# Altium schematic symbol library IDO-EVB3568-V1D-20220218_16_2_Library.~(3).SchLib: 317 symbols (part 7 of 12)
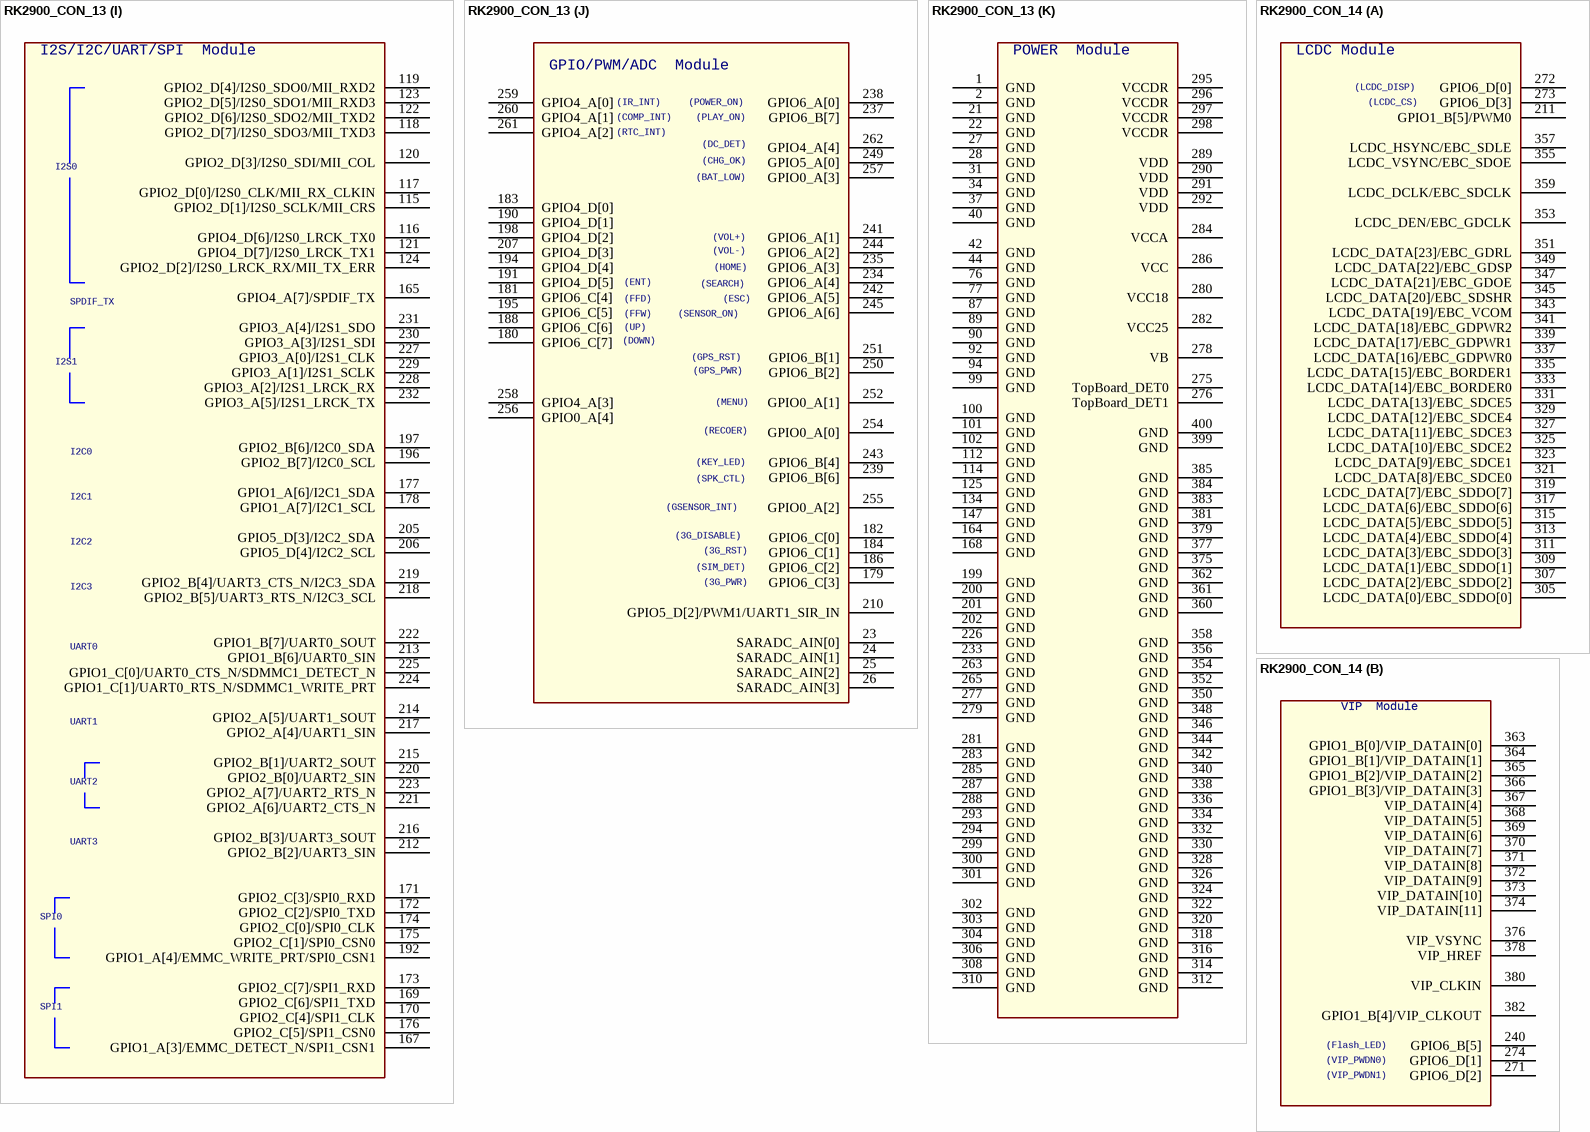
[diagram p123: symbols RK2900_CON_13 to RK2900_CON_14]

## RK2900_CON_13
designator U?
Altium-Right: 240; Altium-Bottom: 690; Altium-Right1: 210; Altium-Bottom1: 440; Altium-Right2: 120; Altium-Bottom2: 650; Altium-Right3: 160; Altium-Bottom3: 390; Altium-Right4: 140; Altium-Bottom4: 270; Altium-Right5: 280; Altium-Bottom5: 520; Altium-Right6: 170; Altium-Right7: 190; Altium-Bottom7: 530; Altium-Right8: 290; Altium-Bottom8: 300; Altium-Right9: 220; Altium-Bottom9: 340; Altium-Right10: 180; Altium-Bottom10: 200
footprint RK2900_TOP
part A pins: 211 GPIO1_B[5]/PWM0, 272 GPIO6_D[0], 273 GPIO6_D[3], 305 LCDC_DATA[0]/EBC_SDDO[0], 307 LCDC_DATA[2]/EBC_SDDO[2], 309 LCDC_DATA[1]/EBC_SDDO[1], 311 LCDC_DATA[3]/EBC_SDDO[3], 313 LCDC_DATA[4]/EBC_SDDO[4], 315 LCDC_DATA[5]/EBC_SDDO[5], 317 LCDC_DATA[6]/EBC_SDDO[6], 319 LCDC_DATA[7]/EBC_SDDO[7], 321 LCDC_DATA[8]/EBC_SDCE0, 323 LCDC_DATA[9]/EBC_SDCE1, 325 LCDC_DATA[10]/EBC_SDCE2, 327 LCDC_DATA[11]/EBC_SDCE3, 329 LCDC_DATA[12]/EBC_SDCE4, 331 LCDC_DATA[13]/EBC_SDCE5, 333 LCDC_DATA[14]/EBC_BORDER0, 335 LCDC_DATA[15]/EBC_BORDER1, 337 LCDC_DATA[16]/EBC_GDPWR0, 339 LCDC_DATA[17]/EBC_GDPWR1, 341 LCDC_DATA[18]/EBC_GDPWR2, 343 LCDC_DATA[19]/EBC_VCOM, 345 LCDC_DATA[20]/EBC_SDSHR, 347 LCDC_DATA[21]/EBC_GDOE, 349 LCDC_DATA[22]/EBC_GDSP, 351 LCDC_DATA[23]/EBC_GDRL, 353 LCDC_DEN/EBC_GDCLK, 355 LCDC_VSYNC/EBC_SDOE, 357 LCDC_HSYNC/EBC_SDLE, 359 LCDC_DCLK/EBC_SDCLK
part B pins: 240 GPIO6_B[5], 271 GPIO6_D[2], 274 GPIO6_D[1], 363 GPIO1_B[0]/VIP_DATAIN[0], 364 GPIO1_B[1]/VIP_DATAIN[1], 365 GPIO1_B[2]/VIP_DATAIN[2], 366 GPIO1_B[3]/VIP_DATAIN[3], 367 VIP_DATAIN[4], 368 VIP_DATAIN[5], 369 VIP_DATAIN[6], 370 VIP_DATAIN[7], 371 VIP_DATAIN[8], 372 VIP_DATAIN[9], 373 VIP_DATAIN[10], 374 VIP_DATAIN[11], 376 VIP_VSYNC, 378 VIP_HREF, 380 VIP_CLKIN, 382 GPIO1_B[4]/VIP_CLKOUT
part C pins: 3 GPIO0_C[6]/EBC_SDCE4/SMC_DATA[14], 4 GPIO0_C[7]/EBC_SDCE5/SMC_DATA[15], 5 GPIO0_C[0]/EBC_GDSP/SMC_DATA[8], 6 GPIO0_C[1]/EBC_GDRL/SMC_DATA[9], 7 GPIO0_B[3]/EBC_BORDER0/SMC_ADDR[3]/HOST_DATA[3], 8 GPIO0_B[4]/EBC_BORDER1/SMC_WEN, 9 GPIO0_D[1]/EBC_GDCLK/SMC_ADDR[4]/HOST_DATA[4], 10 GPIO0_B[2]/EBC_SDCE2/SMC_ADDR[2]/HOST_DATA[2], 11 GPIO0_C[3]/EBC_GDPWR1/SMC_DATA[11], 12 GPIO0_B[7]/EBC_GDOE/SMC_OEN, 13 GPIO0_D[0]/EBC_SDOE/SMC_ADVN, 14 GPIO5_C[6]/EBC_SDDO[6]/SMC_DATA[6], 15 GPIO0_C[5]/EBC_SDCE3/SMC_DATA[13], 16 GPIO0_B[1]/EBC_SDCE1/SMC_ADDR[1]/HOST_DATA[1], 17 GPIO5_C[5]/EBC_SDDO[5]/SMC_DATA[5], 18 GPIO3_D[5]/SMC_ADDR[7]/HOST_DATA[7], 19 GPIO1_A[2]/SMC_CSN1, 20 GPIO0_C[4]/EBC_GDPWR2/SMC_DATA[12], 43 GPIO3_D[6]/SMC_ADDR[8]/HOST_DATA[8], 150 GPIO3_D[4]/HOST_WRN, 151 GPIO3_D[3]/HOST_RDN, 152 GPIO3_D[2]/HOST_CSN, 153 GPIO3_D[7]/SMC_ADDR[9]/HOST_DATA[9], 154 GPIO3_A[6]/SMC_ADDR[14]/HOST_DATA[14], 155 GPIO3_C[7]/SMC_ADDR[17]/HOST_DATA[17], 156 GPIO3_C[3]/SMC_ADDR[10]/HOST_DATA[10], 157 GPIO3_C[4]/SMC_ADDR[11]/HOST_DATA[11], 158 GPIO3_D[1]/SMC_ADDR[19]/HOST_ADDR1, 159 GPIO3_C[5]/SMC_ADDR[12]/HOST_DATA[12], 160 GPIO3_C[2]/SMC_ADDR[13]/HOST_DATA[13], 161 GPIO3_C[6]/SMC_ADDR[16]/HOST_DATA[16], 162 GPIO3_A[7]/SMC_ADDR[15]/HOST_DATA[15], 163 GPIO3_D[0]/SMC_ADDR[18]/HOST_ADDR0, 386 GPIO1_A[1]/SMC_CSN0, 387 GPIO5_C[4]/EBC_SDDO[4]/SMC_DATA[4], 388 GPIO5_D[1]/EBC_SDCLK/SMC_ADDR[6]/HOST_DATA[6], 389 GPIO0_B[5]/EBC_VCOM/SMC_BLSN0, 390 GPIO5_C[0]/EBC_SDDO[0]/SMC_DATA[0], 391 GPIO5_D[0]/EBC_SDLE/SMC_ADDR[5]/HOST_DATA[5], 392 GPIO5_C[1]/EBC_SDDO[1]/SMC_DATA[1], 393 GPIO0_B[6]/EBC_SDSHR/SMC_BLSN1/HOST_INT, 394 GPIO0_C[2]/EBC_GDPWR0/SMC_DATA[10], 395 GPIO5_C[2]/EBC_SDDO[2]/SMC_DATA[2], 396 GPIO5_C[3]/EBC_SDDO[3]/SMC_DATA[3], 397 GPIO5_C[7]/EBC_SDDO[7]/SMC_DATA[7], 398 GPIO0_B[0]/EBC_SDCE0/SMC_ADDR[0]/HOST_DATA[0]
part D pins: 29 OTG_DP, 30 OTG_DM, 32 HOST20_DM, 33 HOST20_DP, 35 HOST11_DM, 36 HOST11_DP, 38 OTG_ID, 39 OTG_VBUS, 41 RTCINT_OUT, 166 GPIO4_A[5]/OTG_DRV_VBUS, 187 GPIO4_A[6]/HOST20_DRV_VBUS, 264 NPOR
part E pins: 45 FLASH_ALE, 46 FLASH_DATA[1], 47 FLASH_RDY, 48 FLASH_RDN, 49 GPIO4_B[4]/FLASH_DATA[12], 50 FLASH_DATA[0], 51 FLASH_DATA[4], 52 GPIO4_B[7]/FLASH_DATA[15], 53 GPIO4_B[5]/FLASH_DATA[13], 54 FLASH_CLE, 55 GPIO4_B[1]/FLASH_DATA[9], 56 FLASH_DATA[5], 57 FLASH_CSN0, 58 FLASH_DATA[6], 59 GPIO4_B[0]/FLASH_DATA[8], 60 FLASH_DATA[7], 61 FLASH_DATA[2], 62 FLASH_DATA[3], 63 GPIO0_D[7]/FLASH_CSN6, 64 FLASH_WP, 65 FLASH_WRN, 66 GPIO4_B[6]/FLASH_DATA[14], 67 GPIO0_D[3]/FLASH_CSN2, 68 GPIO0_D[4]/FLASH_CSN3, 69 GPIO0_D[2]/FLASH_CSN1, 70 GPIO0_D[6]/FLASH_CSN5, 71 GPIO1_A[0]/FLASH_CSN7/MDDR_TQ, 72 GPIO0_A[5]/FLASH_DQS, 73 GPIO0_D[5]/FLASH_CSN4, 74 GPIO4_B[2]/FLASH_DATA[10], 75 GPIO4_B[3]/FLASH_DATA[11], 78 GPIO3_B[3]/EMMC_DATA1, 79 GPIO3_B[1]/EMMC_CMD, 80 GPIO3_B[6]/EMMC_DATA4, 81 GPIO3_C[1]/EMMC_DATA7, 82 GPIO3_B[5]/EMMC_DATA3, 83 GPIO3_B[4]/EMMC_DATA2, 84 GPIO3_B[2]/EMMC_DATA0, 85 GPIO3_C[0]/EMMC_DATA6, 86 GPIO3_B[7]/EMMC_DATA5, 88 GPIO3_B[0]/EMMC_CLKOUT, 203 GPIO1_A[5]/EMMC_PWR_EN/PWM3, 246 GPIO6_A[7]
part F pins: 91 GPIO1_C[2]/SDMMC1_CMD, 93 GPIO1_C[7]/SDMMC1_CLKOUT, 95 GPIO1_C[4]/SDMMC1_DATA1, 96 GPIO1_C[3]/SDMMC1_DATA0, 97 GPIO1_C[6]/SDMMC1_DATA3, 98 GPIO1_C[5]/SDMMC1_DATA2, 103 GPIO1_D[3]/SDMMC0_DATA1, 104 GPIO1_D[1]/SDMMC0_CMD, 105 GPIO1_D[5]/SDMMC0_DATA3, 106 GPIO2_A[1]/SDMMC0_DATA7, 107 GPIO1_D[7]/SDMMC0_DATA5, 108 GPIO1_D[2]/SDMMC0_DATA0, 109 GPIO2_A[0]/SDMMC0_DATA6, 110 GPIO1_D[6]/SDMMC0_DATA4, 111 GPIO1_D[4]/SDMMC0_DATA2, 113 GPIO1_D[0]/SDMMC0_CLKOUT, 185 GPIO5_D[7], 193 GPIO2_A[2]/SDMMC0_DETECT_N, 204 GPIO2_A[3]/SDMMC0_WRITE_PRT/PWM2/UART1_SIR_OUT, 208 GPIO5_D[5]/SDMMC0_PWR_EN, 209 GPIO5_D[6]/SDMMC1_PWR_EN
part G pins: 126 GPIO4_C[7]/RMII_RXD0/MII_RXD0, 127 GPIO4_C[3]/RMII_TXD0/MII_TXD0, 128 GPIO4_C[6]/RMII_RXD1/MII_RXD1, 129 GPIO4_C[1]/RMII_TX_EN/MII_TX_EN, 130 GPIO4_C[0]/RMII_CLKOUT/RMII_CLKIN, 131 GPIO4_C[2]/RMII_TXD1/MII_TXD1, 132 GPIO4_C[5]/RMII_CRS_DVALID/MII_RXD_VALID, 133 GPIO4_C[4]/RMII_RX_ERR/MII_RX_ERR, 148 GPIO5_A[3]/MII_TX_CLKIN, 149 GPIO0_A[6]/MII_MD, 189 GPIO0_A[7]/MII_MDCLK, 236 GPIO5_A[2], 248 GPIO6_B[0], 253 GPIO5_A[1], 266 TRST_N, 267 TCK, 268 TDI, 269 TMS, 270 TDO
part H pins: 135 GPIO5_A[7]/HSADC_DATA2, 136 GPIO5_B[5]/HSADC_DATA8/TS_VALID, 137 GPIO5_A[5]/HSADC_DATA0, 138 GPIO5_B[1]/HSADC_DATA4, 139 GPIO5_B[0]/HSADC_DATA3, 140 GPIO5_A[6]/HSADC_DATA1, 141 GPIO5_B[3]/HSADC_DATA6, 142 GPIO5_B[2]/HSADC_DATA5, 143 GPIO5_B[4]/HSADC_DATA7, 144 GPIO5_A[4]/TS_SYNC, 145 GPIO5_B[6]/HSADC_DATA9/TS_FAIL, 146 GPIO5_B[7]/HSADC_CLKOUT/GPS_CLK, 247 GPIO6_B[3]
part I pins: 115 GPIO2_D[1]/I2S0_SCLK/MII_CRS, 116 GPIO4_D[6]/I2S0_LRCK_TX0, 117 GPIO2_D[0]/I2S0_CLK/MII_RX_CLKIN, 118 GPIO2_D[7]/I2S0_SDO3/MII_TXD3, 119 GPIO2_D[4]/I2S0_SDO0/MII_RXD2, 120 GPIO2_D[3]/I2S0_SDI/MII_COL, 121 GPIO4_D[7]/I2S0_LRCK_TX1, 122 GPIO2_D[6]/I2S0_SDO2/MII_TXD2, 123 GPIO2_D[5]/I2S0_SDO1/MII_RXD3, 124 GPIO2_D[2]/I2S0_LRCK_RX/MII_TX_ERR, 165 GPIO4_A[7]/SPDIF_TX, 167 GPIO1_A[3]/EMMC_DETECT_N/SPI1_CSN1, 169 GPIO2_C[6]/SPI1_TXD, 170 GPIO2_C[4]/SPI1_CLK, 171 GPIO2_C[3]/SPI0_RXD, 172 GPIO2_C[2]/SPI0_TXD, 173 GPIO2_C[7]/SPI1_RXD, 174 GPIO2_C[0]/SPI0_CLK, 175 GPIO2_C[1]/SPI0_CSN0, 176 GPIO2_C[5]/SPI1_CSN0, 177 GPIO1_A[6]/I2C1_SDA, 178 GPIO1_A[7]/I2C1_SCL, 192 GPIO1_A[4]/EMMC_WRITE_PRT/SPI0_CSN1, 196 GPIO2_B[7]/I2C0_SCL, 197 GPIO2_B[6]/I2C0_SDA, 205 GPIO5_D[3]/I2C2_SDA, 206 GPIO5_D[4]/I2C2_SCL, 212 GPIO2_B[2]/UART3_SIN, 213 GPIO1_B[6]/UART0_SIN, 214 GPIO2_A[5]/UART1_SOUT, 215 GPIO2_B[1]/UART2_SOUT, 216 GPIO2_B[3]/UART3_SOUT, 217 GPIO2_A[4]/UART1_SIN, 218 GPIO2_B[5]/UART3_RTS_N/I2C3_SCL, 219 GPIO2_B[4]/UART3_CTS_N/I2C3_SDA, 220 GPIO2_B[0]/UART2_SIN, 221 GPIO2_A[6]/UART2_CTS_N, 222 GPIO1_B[7]/UART0_SOUT, 223 GPIO2_A[7]/UART2_RTS_N, 224 GPIO1_C[1]/UART0_RTS_N/SDMMC1_WRITE_PRT, 225 GPIO1_C[0]/UART0_CTS_N/SDMMC1_DETECT_N, 227 GPIO3_A[0]/I2S1_CLK, 228 GPIO3_A[2]/I2S1_LRCK_RX, 229 GPIO3_A[1]/I2S1_SCLK, 230 GPIO3_A[3]/I2S1_SDI, 231 GPIO3_A[4]/I2S1_SDO, 232 GPIO3_A[5]/I2S1_LRCK_TX
part J pins: 23 SARADC_AIN[0], 24 SARADC_AIN[1], 25 SARADC_AIN[2], 26 SARADC_AIN[3], 179 GPIO6_C[3], 180 GPIO6_C[7], 181 GPIO6_C[4], 182 GPIO6_C[0], 183 GPIO4_D[0], 184 GPIO6_C[1], 186 GPIO6_C[2], 188 GPIO6_C[6], 190 GPIO4_D[1], 191 GPIO4_D[5], 194 GPIO4_D[4], 195 GPIO6_C[5], 198 GPIO4_D[2], 207 GPIO4_D[3], 210 GPIO5_D[2]/PWM1/UART1_SIR_IN, 234 GPIO6_A[4], 235 GPIO6_A[3], 237 GPIO6_B[7], 238 GPIO6_A[0], 239 GPIO6_B[6], 241 GPIO6_A[1], 242 GPIO6_A[5], 243 GPIO6_B[4], 244 GPIO6_A[2], 245 GPIO6_A[6], 249 GPIO5_A[0], 250 GPIO6_B[2], 251 GPIO6_B[1], 252 GPIO0_A[1], 254 GPIO0_A[0], 255 GPIO0_A[2], 256 GPIO0_A[4], 257 GPIO0_A[3], 258 GPIO4_A[3], 259 GPIO4_A[0], 260 GPIO4_A[1], 261 GPIO4_A[2], 262 GPIO4_A[4]
part K pins: 1 GND, 2 GND, 21 GND, 22 GND, 27 GND, 28 GND, 31 GND, 34 GND, 37 GND, 40 GND, 42 GND, 44 GND, 76 GND, 77 GND, 87 GND, 89 GND, 90 GND, 92 GND, 94 GND, 99 GND, 100 GND, 101 GND, 102 GND, 112 GND, 114 GND, 125 GND, 134 GND, 147 GND, 164 GND, 168 GND, 199 GND, 200 GND, 201 GND, 202 GND, 226 GND, 233 GND, 263 GND, 265 GND, 275 TopBoard_DET0, 276 TopBoard_DET1, 277 GND, 278 VB, 279 GND, 280 VCC18, 281 GND, 282 VCC25, 283 GND, 284 VCCA, 285 GND, 286 VCC, 287 GND, 288 GND, 289 VDD, 290 VDD, 291 VDD, 292 VDD, 293 GND, 294 GND, 295 VCCDR, 296 VCCDR, 297 VCCDR, 298 VCCDR, 299 GND, 300 GND, 301 GND, 302 GND, 303 GND, 304 GND, 306 GND, 308 GND, 310 GND, 312 GND, 314 GND, 316 GND, 318 GND, 320 GND, 322 GND, 324 GND, 326 GND, 328 GND, 330 GND, 332 GND, 334 GND, 336 GND, 338 GND, 340 GND, 342 GND, 344 GND, 346 GND, 348 GND, 350 GND, 352 GND, 354 GND, 356 GND, 358 GND, 360 GND, 361 GND, 362 GND, 375 GND, 377 GND, 379 GND, 381 GND, 383 GND, 384 GND, 385 GND, 399 GND, 400 GND

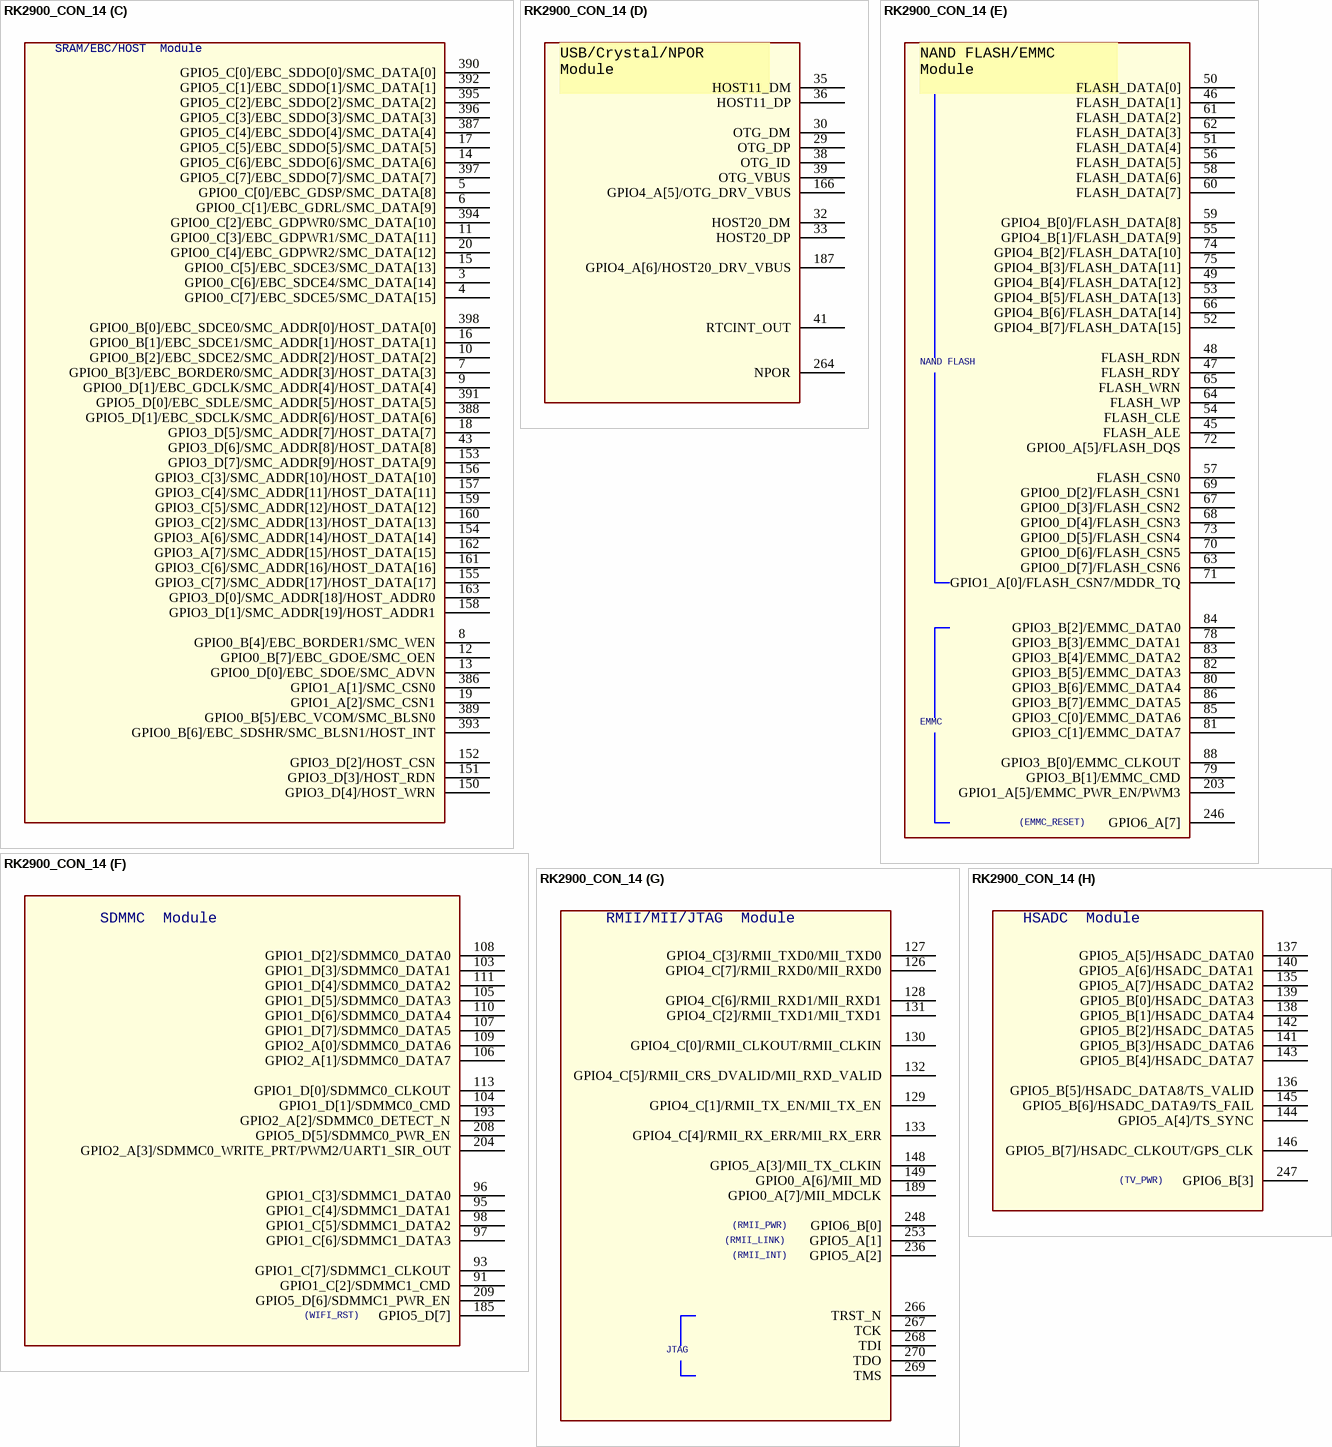
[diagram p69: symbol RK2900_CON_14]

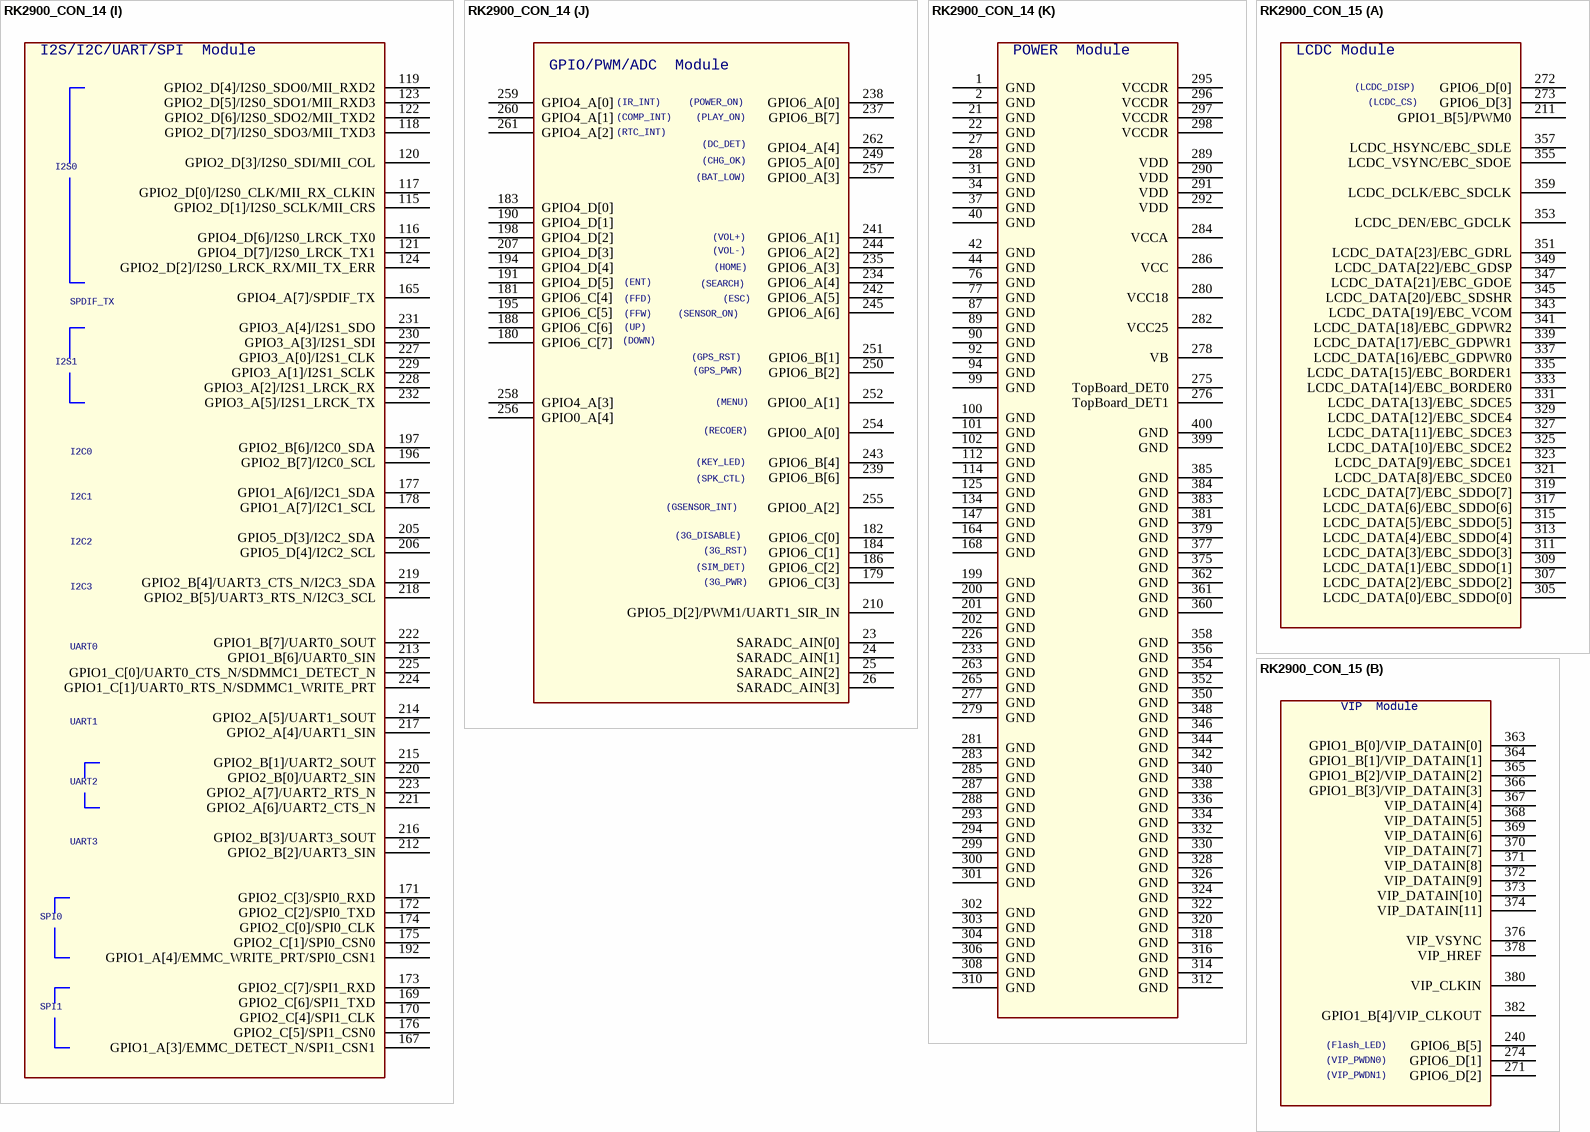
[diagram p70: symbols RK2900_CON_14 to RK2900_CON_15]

## RK2900_CON_14
designator U?
Altium-Right: 210; Altium-Bottom: 440; Altium-Right1: 120; Altium-Bottom1: 650; Altium-Right2: 160; Altium-Bottom2: 390; Altium-Right3: 140; Altium-Bottom3: 270; Altium-Right4: 280; Altium-Bottom4: 520; Altium-Right5: 170; Altium-Bottom5: 240; Altium-Right6: 190; Altium-Bottom6: 530; Altium-Right7: 290; Altium-Bottom7: 300; Altium-Right8: 220; Altium-Bottom8: 340; Altium-Right9: 180; Altium-Bottom9: 200; Altium-Bottom10: 690
footprint RK2900_TOP
part A pins: 211 GPIO1_B[5]/PWM0, 272 GPIO6_D[0], 273 GPIO6_D[3], 305 LCDC_DATA[0]/EBC_SDDO[0], 307 LCDC_DATA[2]/EBC_SDDO[2], 309 LCDC_DATA[1]/EBC_SDDO[1], 311 LCDC_DATA[3]/EBC_SDDO[3], 313 LCDC_DATA[4]/EBC_SDDO[4], 315 LCDC_DATA[5]/EBC_SDDO[5], 317 LCDC_DATA[6]/EBC_SDDO[6], 319 LCDC_DATA[7]/EBC_SDDO[7], 321 LCDC_DATA[8]/EBC_SDCE0, 323 LCDC_DATA[9]/EBC_SDCE1, 325 LCDC_DATA[10]/EBC_SDCE2, 327 LCDC_DATA[11]/EBC_SDCE3, 329 LCDC_DATA[12]/EBC_SDCE4, 331 LCDC_DATA[13]/EBC_SDCE5, 333 LCDC_DATA[14]/EBC_BORDER0, 335 LCDC_DATA[15]/EBC_BORDER1, 337 LCDC_DATA[16]/EBC_GDPWR0, 339 LCDC_DATA[17]/EBC_GDPWR1, 341 LCDC_DATA[18]/EBC_GDPWR2, 343 LCDC_DATA[19]/EBC_VCOM, 345 LCDC_DATA[20]/EBC_SDSHR, 347 LCDC_DATA[21]/EBC_GDOE, 349 LCDC_DATA[22]/EBC_GDSP, 351 LCDC_DATA[23]/EBC_GDRL, 353 LCDC_DEN/EBC_GDCLK, 355 LCDC_VSYNC/EBC_SDOE, 357 LCDC_HSYNC/EBC_SDLE, 359 LCDC_DCLK/EBC_SDCLK
part B pins: 240 GPIO6_B[5], 271 GPIO6_D[2], 274 GPIO6_D[1], 363 GPIO1_B[0]/VIP_DATAIN[0], 364 GPIO1_B[1]/VIP_DATAIN[1], 365 GPIO1_B[2]/VIP_DATAIN[2], 366 GPIO1_B[3]/VIP_DATAIN[3], 367 VIP_DATAIN[4], 368 VIP_DATAIN[5], 369 VIP_DATAIN[6], 370 VIP_DATAIN[7], 371 VIP_DATAIN[8], 372 VIP_DATAIN[9], 373 VIP_DATAIN[10], 374 VIP_DATAIN[11], 376 VIP_VSYNC, 378 VIP_HREF, 380 VIP_CLKIN, 382 GPIO1_B[4]/VIP_CLKOUT
part C pins: 3 GPIO0_C[6]/EBC_SDCE4/SMC_DATA[14], 4 GPIO0_C[7]/EBC_SDCE5/SMC_DATA[15], 5 GPIO0_C[0]/EBC_GDSP/SMC_DATA[8], 6 GPIO0_C[1]/EBC_GDRL/SMC_DATA[9], 7 GPIO0_B[3]/EBC_BORDER0/SMC_ADDR[3]/HOST_DATA[3], 8 GPIO0_B[4]/EBC_BORDER1/SMC_WEN, 9 GPIO0_D[1]/EBC_GDCLK/SMC_ADDR[4]/HOST_DATA[4], 10 GPIO0_B[2]/EBC_SDCE2/SMC_ADDR[2]/HOST_DATA[2], 11 GPIO0_C[3]/EBC_GDPWR1/SMC_DATA[11], 12 GPIO0_B[7]/EBC_GDOE/SMC_OEN, 13 GPIO0_D[0]/EBC_SDOE/SMC_ADVN, 14 GPIO5_C[6]/EBC_SDDO[6]/SMC_DATA[6], 15 GPIO0_C[5]/EBC_SDCE3/SMC_DATA[13], 16 GPIO0_B[1]/EBC_SDCE1/SMC_ADDR[1]/HOST_DATA[1], 17 GPIO5_C[5]/EBC_SDDO[5]/SMC_DATA[5], 18 GPIO3_D[5]/SMC_ADDR[7]/HOST_DATA[7], 19 GPIO1_A[2]/SMC_CSN1, 20 GPIO0_C[4]/EBC_GDPWR2/SMC_DATA[12], 43 GPIO3_D[6]/SMC_ADDR[8]/HOST_DATA[8], 150 GPIO3_D[4]/HOST_WRN, 151 GPIO3_D[3]/HOST_RDN, 152 GPIO3_D[2]/HOST_CSN, 153 GPIO3_D[7]/SMC_ADDR[9]/HOST_DATA[9], 154 GPIO3_A[6]/SMC_ADDR[14]/HOST_DATA[14], 155 GPIO3_C[7]/SMC_ADDR[17]/HOST_DATA[17], 156 GPIO3_C[3]/SMC_ADDR[10]/HOST_DATA[10], 157 GPIO3_C[4]/SMC_ADDR[11]/HOST_DATA[11], 158 GPIO3_D[1]/SMC_ADDR[19]/HOST_ADDR1, 159 GPIO3_C[5]/SMC_ADDR[12]/HOST_DATA[12], 160 GPIO3_C[2]/SMC_ADDR[13]/HOST_DATA[13], 161 GPIO3_C[6]/SMC_ADDR[16]/HOST_DATA[16], 162 GPIO3_A[7]/SMC_ADDR[15]/HOST_DATA[15], 163 GPIO3_D[0]/SMC_ADDR[18]/HOST_ADDR0, 386 GPIO1_A[1]/SMC_CSN0, 387 GPIO5_C[4]/EBC_SDDO[4]/SMC_DATA[4], 388 GPIO5_D[1]/EBC_SDCLK/SMC_ADDR[6]/HOST_DATA[6], 389 GPIO0_B[5]/EBC_VCOM/SMC_BLSN0, 390 GPIO5_C[0]/EBC_SDDO[0]/SMC_DATA[0], 391 GPIO5_D[0]/EBC_SDLE/SMC_ADDR[5]/HOST_DATA[5], 392 GPIO5_C[1]/EBC_SDDO[1]/SMC_DATA[1], 393 GPIO0_B[6]/EBC_SDSHR/SMC_BLSN1/HOST_INT, 394 GPIO0_C[2]/EBC_GDPWR0/SMC_DATA[10], 395 GPIO5_C[2]/EBC_SDDO[2]/SMC_DATA[2], 396 GPIO5_C[3]/EBC_SDDO[3]/SMC_DATA[3], 397 GPIO5_C[7]/EBC_SDDO[7]/SMC_DATA[7], 398 GPIO0_B[0]/EBC_SDCE0/SMC_ADDR[0]/HOST_DATA[0]
part D pins: 29 OTG_DP, 30 OTG_DM, 32 HOST20_DM, 33 HOST20_DP, 35 HOST11_DM, 36 HOST11_DP, 38 OTG_ID, 39 OTG_VBUS, 41 RTCINT_OUT, 166 GPIO4_A[5]/OTG_DRV_VBUS, 187 GPIO4_A[6]/HOST20_DRV_VBUS, 264 NPOR
part E pins: 45 FLASH_ALE, 46 FLASH_DATA[1], 47 FLASH_RDY, 48 FLASH_RDN, 49 GPIO4_B[4]/FLASH_DATA[12], 50 FLASH_DATA[0], 51 FLASH_DATA[4], 52 GPIO4_B[7]/FLASH_DATA[15], 53 GPIO4_B[5]/FLASH_DATA[13], 54 FLASH_CLE, 55 GPIO4_B[1]/FLASH_DATA[9], 56 FLASH_DATA[5], 57 FLASH_CSN0, 58 FLASH_DATA[6], 59 GPIO4_B[0]/FLASH_DATA[8], 60 FLASH_DATA[7], 61 FLASH_DATA[2], 62 FLASH_DATA[3], 63 GPIO0_D[7]/FLASH_CSN6, 64 FLASH_WP, 65 FLASH_WRN, 66 GPIO4_B[6]/FLASH_DATA[14], 67 GPIO0_D[3]/FLASH_CSN2, 68 GPIO0_D[4]/FLASH_CSN3, 69 GPIO0_D[2]/FLASH_CSN1, 70 GPIO0_D[6]/FLASH_CSN5, 71 GPIO1_A[0]/FLASH_CSN7/MDDR_TQ, 72 GPIO0_A[5]/FLASH_DQS, 73 GPIO0_D[5]/FLASH_CSN4, 74 GPIO4_B[2]/FLASH_DATA[10], 75 GPIO4_B[3]/FLASH_DATA[11], 78 GPIO3_B[3]/EMMC_DATA1, 79 GPIO3_B[1]/EMMC_CMD, 80 GPIO3_B[6]/EMMC_DATA4, 81 GPIO3_C[1]/EMMC_DATA7, 82 GPIO3_B[5]/EMMC_DATA3, 83 GPIO3_B[4]/EMMC_DATA2, 84 GPIO3_B[2]/EMMC_DATA0, 85 GPIO3_C[0]/EMMC_DATA6, 86 GPIO3_B[7]/EMMC_DATA5, 88 GPIO3_B[0]/EMMC_CLKOUT, 203 GPIO1_A[5]/EMMC_PWR_EN/PWM3, 246 GPIO6_A[7]
part F pins: 91 GPIO1_C[2]/SDMMC1_CMD, 93 GPIO1_C[7]/SDMMC1_CLKOUT, 95 GPIO1_C[4]/SDMMC1_DATA1, 96 GPIO1_C[3]/SDMMC1_DATA0, 97 GPIO1_C[6]/SDMMC1_DATA3, 98 GPIO1_C[5]/SDMMC1_DATA2, 103 GPIO1_D[3]/SDMMC0_DATA1, 104 GPIO1_D[1]/SDMMC0_CMD, 105 GPIO1_D[5]/SDMMC0_DATA3, 106 GPIO2_A[1]/SDMMC0_DATA7, 107 GPIO1_D[7]/SDMMC0_DATA5, 108 GPIO1_D[2]/SDMMC0_DATA0, 109 GPIO2_A[0]/SDMMC0_DATA6, 110 GPIO1_D[6]/SDMMC0_DATA4, 111 GPIO1_D[4]/SDMMC0_DATA2, 113 GPIO1_D[0]/SDMMC0_CLKOUT, 185 GPIO5_D[7], 193 GPIO2_A[2]/SDMMC0_DETECT_N, 204 GPIO2_A[3]/SDMMC0_WRITE_PRT/PWM2/UART1_SIR_OUT, 208 GPIO5_D[5]/SDMMC0_PWR_EN, 209 GPIO5_D[6]/SDMMC1_PWR_EN
part G pins: 126 GPIO4_C[7]/RMII_RXD0/MII_RXD0, 127 GPIO4_C[3]/RMII_TXD0/MII_TXD0, 128 GPIO4_C[6]/RMII_RXD1/MII_RXD1, 129 GPIO4_C[1]/RMII_TX_EN/MII_TX_EN, 130 GPIO4_C[0]/RMII_CLKOUT/RMII_CLKIN, 131 GPIO4_C[2]/RMII_TXD1/MII_TXD1, 132 GPIO4_C[5]/RMII_CRS_DVALID/MII_RXD_VALID, 133 GPIO4_C[4]/RMII_RX_ERR/MII_RX_ERR, 148 GPIO5_A[3]/MII_TX_CLKIN, 149 GPIO0_A[6]/MII_MD, 189 GPIO0_A[7]/MII_MDCLK, 236 GPIO5_A[2], 248 GPIO6_B[0], 253 GPIO5_A[1], 266 TRST_N, 267 TCK, 268 TDI, 269 TMS, 270 TDO
part H pins: 135 GPIO5_A[7]/HSADC_DATA2, 136 GPIO5_B[5]/HSADC_DATA8/TS_VALID, 137 GPIO5_A[5]/HSADC_DATA0, 138 GPIO5_B[1]/HSADC_DATA4, 139 GPIO5_B[0]/HSADC_DATA3, 140 GPIO5_A[6]/HSADC_DATA1, 141 GPIO5_B[3]/HSADC_DATA6, 142 GPIO5_B[2]/HSADC_DATA5, 143 GPIO5_B[4]/HSADC_DATA7, 144 GPIO5_A[4]/TS_SYNC, 145 GPIO5_B[6]/HSADC_DATA9/TS_FAIL, 146 GPIO5_B[7]/HSADC_CLKOUT/GPS_CLK, 247 GPIO6_B[3]
part I pins: 115 GPIO2_D[1]/I2S0_SCLK/MII_CRS, 116 GPIO4_D[6]/I2S0_LRCK_TX0, 117 GPIO2_D[0]/I2S0_CLK/MII_RX_CLKIN, 118 GPIO2_D[7]/I2S0_SDO3/MII_TXD3, 119 GPIO2_D[4]/I2S0_SDO0/MII_RXD2, 120 GPIO2_D[3]/I2S0_SDI/MII_COL, 121 GPIO4_D[7]/I2S0_LRCK_TX1, 122 GPIO2_D[6]/I2S0_SDO2/MII_TXD2, 123 GPIO2_D[5]/I2S0_SDO1/MII_RXD3, 124 GPIO2_D[2]/I2S0_LRCK_RX/MII_TX_ERR, 165 GPIO4_A[7]/SPDIF_TX, 167 GPIO1_A[3]/EMMC_DETECT_N/SPI1_CSN1, 169 GPIO2_C[6]/SPI1_TXD, 170 GPIO2_C[4]/SPI1_CLK, 171 GPIO2_C[3]/SPI0_RXD, 172 GPIO2_C[2]/SPI0_TXD, 173 GPIO2_C[7]/SPI1_RXD, 174 GPIO2_C[0]/SPI0_CLK, 175 GPIO2_C[1]/SPI0_CSN0, 176 GPIO2_C[5]/SPI1_CSN0, 177 GPIO1_A[6]/I2C1_SDA, 178 GPIO1_A[7]/I2C1_SCL, 192 GPIO1_A[4]/EMMC_WRITE_PRT/SPI0_CSN1, 196 GPIO2_B[7]/I2C0_SCL, 197 GPIO2_B[6]/I2C0_SDA, 205 GPIO5_D[3]/I2C2_SDA, 206 GPIO5_D[4]/I2C2_SCL, 212 GPIO2_B[2]/UART3_SIN, 213 GPIO1_B[6]/UART0_SIN, 214 GPIO2_A[5]/UART1_SOUT, 215 GPIO2_B[1]/UART2_SOUT, 216 GPIO2_B[3]/UART3_SOUT, 217 GPIO2_A[4]/UART1_SIN, 218 GPIO2_B[5]/UART3_RTS_N/I2C3_SCL, 219 GPIO2_B[4]/UART3_CTS_N/I2C3_SDA, 220 GPIO2_B[0]/UART2_SIN, 221 GPIO2_A[6]/UART2_CTS_N, 222 GPIO1_B[7]/UART0_SOUT, 223 GPIO2_A[7]/UART2_RTS_N, 224 GPIO1_C[1]/UART0_RTS_N/SDMMC1_WRITE_PRT, 225 GPIO1_C[0]/UART0_CTS_N/SDMMC1_DETECT_N, 227 GPIO3_A[0]/I2S1_CLK, 228 GPIO3_A[2]/I2S1_LRCK_RX, 229 GPIO3_A[1]/I2S1_SCLK, 230 GPIO3_A[3]/I2S1_SDI, 231 GPIO3_A[4]/I2S1_SDO, 232 GPIO3_A[5]/I2S1_LRCK_TX
part J pins: 23 SARADC_AIN[0], 24 SARADC_AIN[1], 25 SARADC_AIN[2], 26 SARADC_AIN[3], 179 GPIO6_C[3], 180 GPIO6_C[7], 181 GPIO6_C[4], 182 GPIO6_C[0], 183 GPIO4_D[0], 184 GPIO6_C[1], 186 GPIO6_C[2], 188 GPIO6_C[6], 190 GPIO4_D[1], 191 GPIO4_D[5], 194 GPIO4_D[4], 195 GPIO6_C[5], 198 GPIO4_D[2], 207 GPIO4_D[3], 210 GPIO5_D[2]/PWM1/UART1_SIR_IN, 234 GPIO6_A[4], 235 GPIO6_A[3], 237 GPIO6_B[7], 238 GPIO6_A[0], 239 GPIO6_B[6], 241 GPIO6_A[1], 242 GPIO6_A[5], 243 GPIO6_B[4], 244 GPIO6_A[2], 245 GPIO6_A[6], 249 GPIO5_A[0], 250 GPIO6_B[2], 251 GPIO6_B[1], 252 GPIO0_A[1], 254 GPIO0_A[0], 255 GPIO0_A[2], 256 GPIO0_A[4], 257 GPIO0_A[3], 258 GPIO4_A[3], 259 GPIO4_A[0], 260 GPIO4_A[1], 261 GPIO4_A[2], 262 GPIO4_A[4]
part K pins: 1 GND, 2 GND, 21 GND, 22 GND, 27 GND, 28 GND, 31 GND, 34 GND, 37 GND, 40 GND, 42 GND, 44 GND, 76 GND, 77 GND, 87 GND, 89 GND, 90 GND, 92 GND, 94 GND, 99 GND, 100 GND, 101 GND, 102 GND, 112 GND, 114 GND, 125 GND, 134 GND, 147 GND, 164 GND, 168 GND, 199 GND, 200 GND, 201 GND, 202 GND, 226 GND, 233 GND, 263 GND, 265 GND, 275 TopBoard_DET0, 276 TopBoard_DET1, 277 GND, 278 VB, 279 GND, 280 VCC18, 281 GND, 282 VCC25, 283 GND, 284 VCCA, 285 GND, 286 VCC, 287 GND, 288 GND, 289 VDD, 290 VDD, 291 VDD, 292 VDD, 293 GND, 294 GND, 295 VCCDR, 296 VCCDR, 297 VCCDR, 298 VCCDR, 299 GND, 300 GND, 301 GND, 302 GND, 303 GND, 304 GND, 306 GND, 308 GND, 310 GND, 312 GND, 314 GND, 316 GND, 318 GND, 320 GND, 322 GND, 324 GND, 326 GND, 328 GND, 330 GND, 332 GND, 334 GND, 336 GND, 338 GND, 340 GND, 342 GND, 344 GND, 346 GND, 348 GND, 350 GND, 352 GND, 354 GND, 356 GND, 358 GND, 360 GND, 361 GND, 362 GND, 375 GND, 377 GND, 379 GND, 381 GND, 383 GND, 384 GND, 385 GND, 399 GND, 400 GND

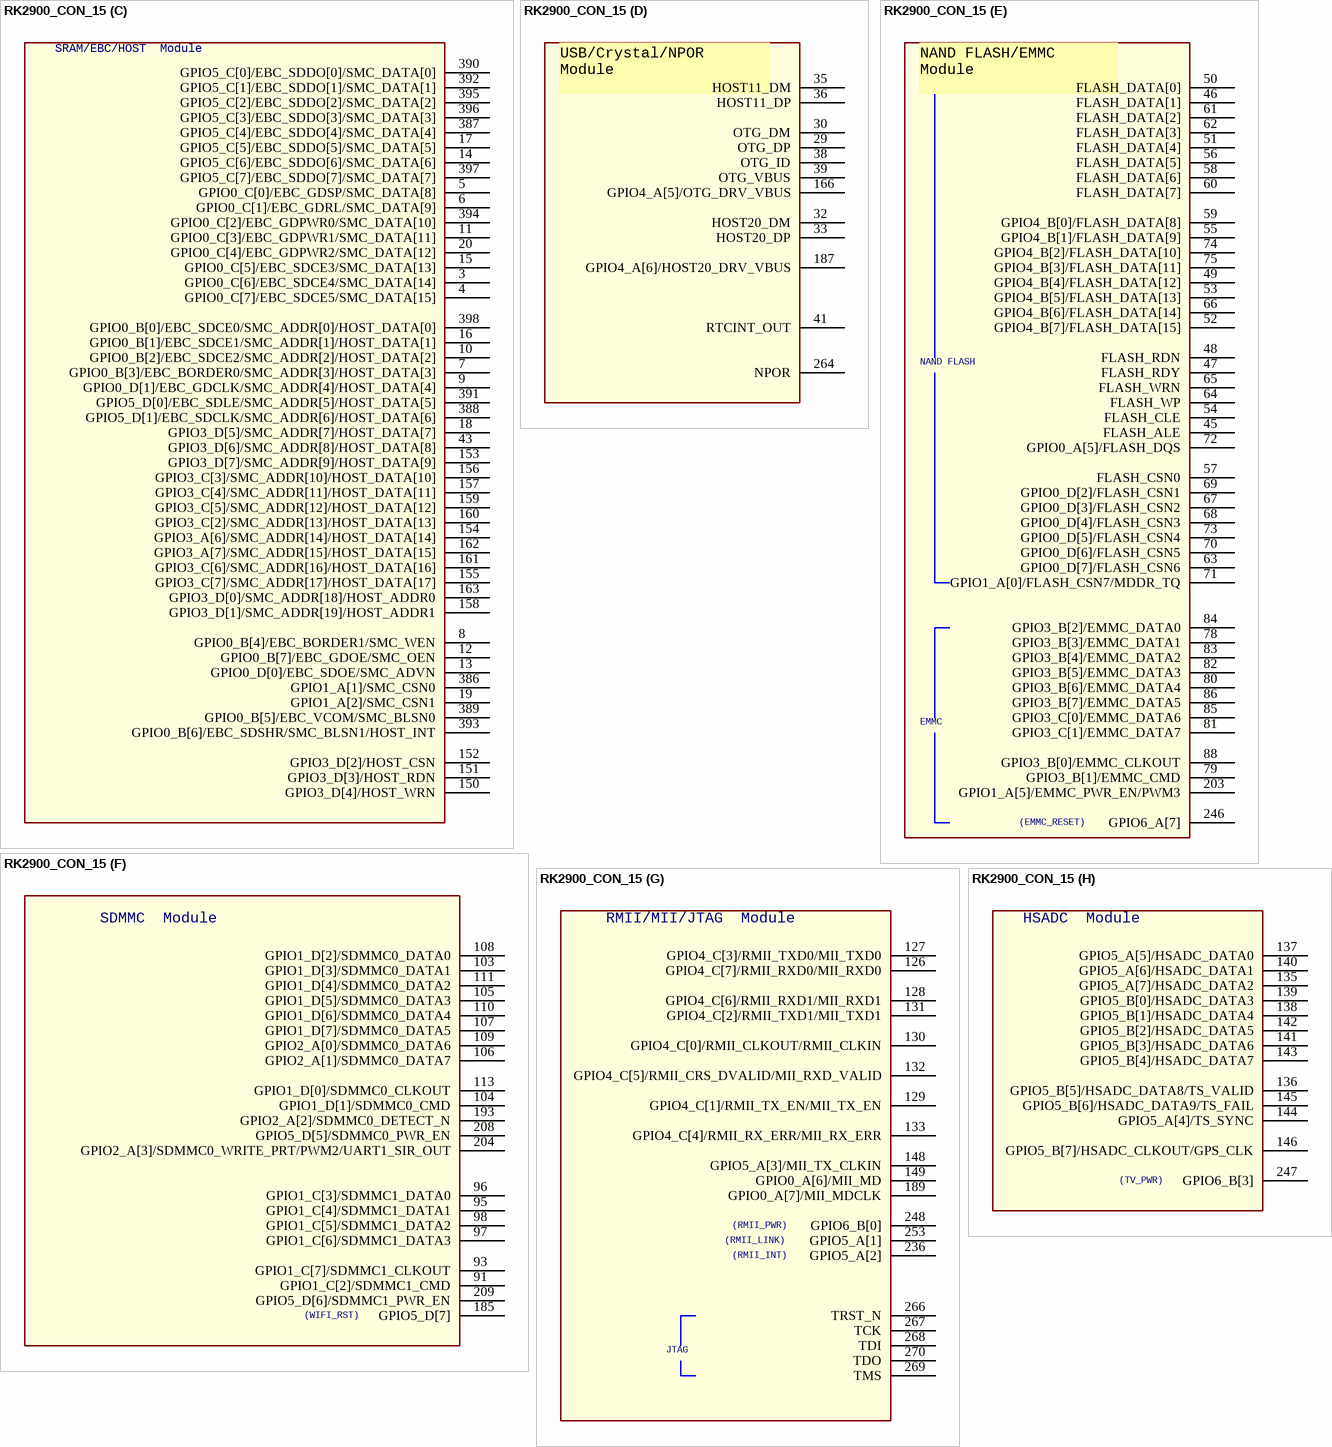
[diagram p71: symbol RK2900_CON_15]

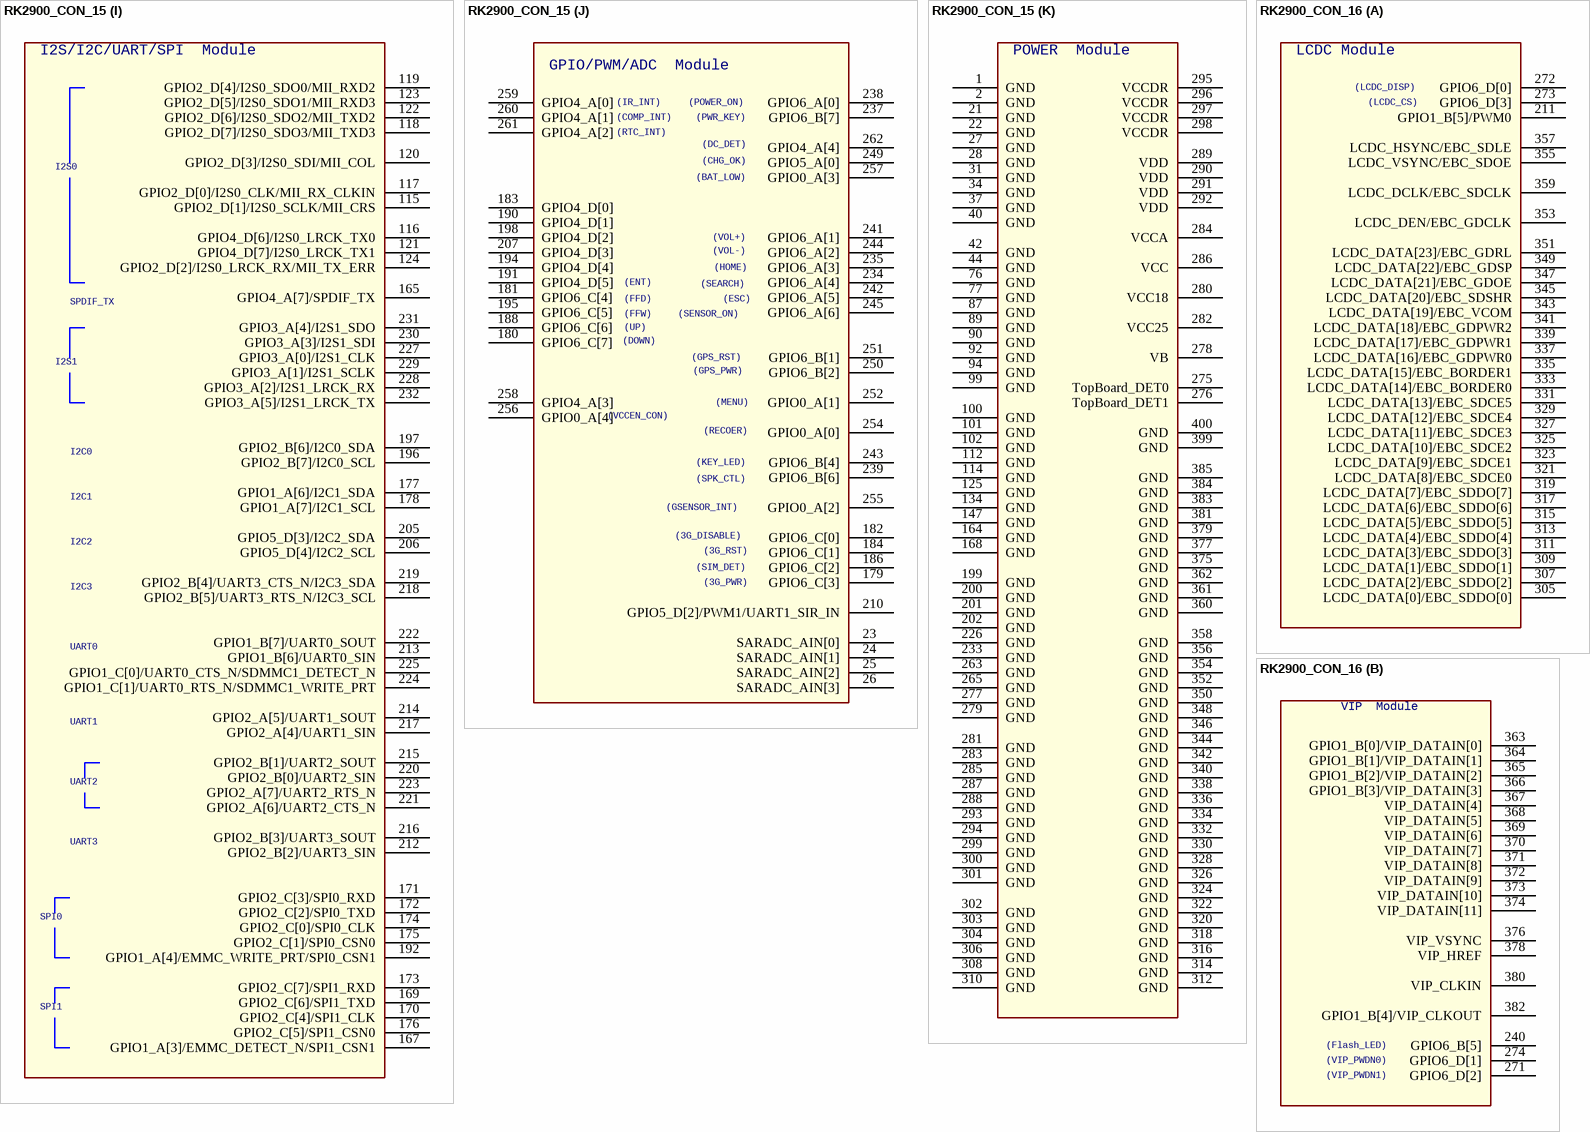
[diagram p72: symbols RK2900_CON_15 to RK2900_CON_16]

## RK2900_CON_15
designator U?
Altium-Right: 120; Altium-Bottom: 650; Altium-Right1: 160; Altium-Bottom1: 390; Altium-Right2: 140; Altium-Bottom2: 270; Altium-Right3: 280; Altium-Bottom3: 520; Altium-Right4: 170; Altium-Bottom4: 240; Altium-Right5: 190; Altium-Bottom5: 530; Altium-Right6: 290; Altium-Bottom6: 300; Altium-Right7: 220; Altium-Bottom7: 340; Altium-Right8: 180; Altium-Bottom8: 200; Altium-Bottom9: 690; Altium-Right10: 210; Altium-Bottom10: 440
footprint RK2900_TOP
part A pins: 211 GPIO1_B[5]/PWM0, 272 GPIO6_D[0], 273 GPIO6_D[3], 305 LCDC_DATA[0]/EBC_SDDO[0], 307 LCDC_DATA[2]/EBC_SDDO[2], 309 LCDC_DATA[1]/EBC_SDDO[1], 311 LCDC_DATA[3]/EBC_SDDO[3], 313 LCDC_DATA[4]/EBC_SDDO[4], 315 LCDC_DATA[5]/EBC_SDDO[5], 317 LCDC_DATA[6]/EBC_SDDO[6], 319 LCDC_DATA[7]/EBC_SDDO[7], 321 LCDC_DATA[8]/EBC_SDCE0, 323 LCDC_DATA[9]/EBC_SDCE1, 325 LCDC_DATA[10]/EBC_SDCE2, 327 LCDC_DATA[11]/EBC_SDCE3, 329 LCDC_DATA[12]/EBC_SDCE4, 331 LCDC_DATA[13]/EBC_SDCE5, 333 LCDC_DATA[14]/EBC_BORDER0, 335 LCDC_DATA[15]/EBC_BORDER1, 337 LCDC_DATA[16]/EBC_GDPWR0, 339 LCDC_DATA[17]/EBC_GDPWR1, 341 LCDC_DATA[18]/EBC_GDPWR2, 343 LCDC_DATA[19]/EBC_VCOM, 345 LCDC_DATA[20]/EBC_SDSHR, 347 LCDC_DATA[21]/EBC_GDOE, 349 LCDC_DATA[22]/EBC_GDSP, 351 LCDC_DATA[23]/EBC_GDRL, 353 LCDC_DEN/EBC_GDCLK, 355 LCDC_VSYNC/EBC_SDOE, 357 LCDC_HSYNC/EBC_SDLE, 359 LCDC_DCLK/EBC_SDCLK
part B pins: 240 GPIO6_B[5], 271 GPIO6_D[2], 274 GPIO6_D[1], 363 GPIO1_B[0]/VIP_DATAIN[0], 364 GPIO1_B[1]/VIP_DATAIN[1], 365 GPIO1_B[2]/VIP_DATAIN[2], 366 GPIO1_B[3]/VIP_DATAIN[3], 367 VIP_DATAIN[4], 368 VIP_DATAIN[5], 369 VIP_DATAIN[6], 370 VIP_DATAIN[7], 371 VIP_DATAIN[8], 372 VIP_DATAIN[9], 373 VIP_DATAIN[10], 374 VIP_DATAIN[11], 376 VIP_VSYNC, 378 VIP_HREF, 380 VIP_CLKIN, 382 GPIO1_B[4]/VIP_CLKOUT
part C pins: 3 GPIO0_C[6]/EBC_SDCE4/SMC_DATA[14], 4 GPIO0_C[7]/EBC_SDCE5/SMC_DATA[15], 5 GPIO0_C[0]/EBC_GDSP/SMC_DATA[8], 6 GPIO0_C[1]/EBC_GDRL/SMC_DATA[9], 7 GPIO0_B[3]/EBC_BORDER0/SMC_ADDR[3]/HOST_DATA[3], 8 GPIO0_B[4]/EBC_BORDER1/SMC_WEN, 9 GPIO0_D[1]/EBC_GDCLK/SMC_ADDR[4]/HOST_DATA[4], 10 GPIO0_B[2]/EBC_SDCE2/SMC_ADDR[2]/HOST_DATA[2], 11 GPIO0_C[3]/EBC_GDPWR1/SMC_DATA[11], 12 GPIO0_B[7]/EBC_GDOE/SMC_OEN, 13 GPIO0_D[0]/EBC_SDOE/SMC_ADVN, 14 GPIO5_C[6]/EBC_SDDO[6]/SMC_DATA[6], 15 GPIO0_C[5]/EBC_SDCE3/SMC_DATA[13], 16 GPIO0_B[1]/EBC_SDCE1/SMC_ADDR[1]/HOST_DATA[1], 17 GPIO5_C[5]/EBC_SDDO[5]/SMC_DATA[5], 18 GPIO3_D[5]/SMC_ADDR[7]/HOST_DATA[7], 19 GPIO1_A[2]/SMC_CSN1, 20 GPIO0_C[4]/EBC_GDPWR2/SMC_DATA[12], 43 GPIO3_D[6]/SMC_ADDR[8]/HOST_DATA[8], 150 GPIO3_D[4]/HOST_WRN, 151 GPIO3_D[3]/HOST_RDN, 152 GPIO3_D[2]/HOST_CSN, 153 GPIO3_D[7]/SMC_ADDR[9]/HOST_DATA[9], 154 GPIO3_A[6]/SMC_ADDR[14]/HOST_DATA[14], 155 GPIO3_C[7]/SMC_ADDR[17]/HOST_DATA[17], 156 GPIO3_C[3]/SMC_ADDR[10]/HOST_DATA[10], 157 GPIO3_C[4]/SMC_ADDR[11]/HOST_DATA[11], 158 GPIO3_D[1]/SMC_ADDR[19]/HOST_ADDR1, 159 GPIO3_C[5]/SMC_ADDR[12]/HOST_DATA[12], 160 GPIO3_C[2]/SMC_ADDR[13]/HOST_DATA[13], 161 GPIO3_C[6]/SMC_ADDR[16]/HOST_DATA[16], 162 GPIO3_A[7]/SMC_ADDR[15]/HOST_DATA[15], 163 GPIO3_D[0]/SMC_ADDR[18]/HOST_ADDR0, 386 GPIO1_A[1]/SMC_CSN0, 387 GPIO5_C[4]/EBC_SDDO[4]/SMC_DATA[4], 388 GPIO5_D[1]/EBC_SDCLK/SMC_ADDR[6]/HOST_DATA[6], 389 GPIO0_B[5]/EBC_VCOM/SMC_BLSN0, 390 GPIO5_C[0]/EBC_SDDO[0]/SMC_DATA[0], 391 GPIO5_D[0]/EBC_SDLE/SMC_ADDR[5]/HOST_DATA[5], 392 GPIO5_C[1]/EBC_SDDO[1]/SMC_DATA[1], 393 GPIO0_B[6]/EBC_SDSHR/SMC_BLSN1/HOST_INT, 394 GPIO0_C[2]/EBC_GDPWR0/SMC_DATA[10], 395 GPIO5_C[2]/EBC_SDDO[2]/SMC_DATA[2], 396 GPIO5_C[3]/EBC_SDDO[3]/SMC_DATA[3], 397 GPIO5_C[7]/EBC_SDDO[7]/SMC_DATA[7], 398 GPIO0_B[0]/EBC_SDCE0/SMC_ADDR[0]/HOST_DATA[0]
part D pins: 29 OTG_DP, 30 OTG_DM, 32 HOST20_DM, 33 HOST20_DP, 35 HOST11_DM, 36 HOST11_DP, 38 OTG_ID, 39 OTG_VBUS, 41 RTCINT_OUT, 166 GPIO4_A[5]/OTG_DRV_VBUS, 187 GPIO4_A[6]/HOST20_DRV_VBUS, 264 NPOR
part E pins: 45 FLASH_ALE, 46 FLASH_DATA[1], 47 FLASH_RDY, 48 FLASH_RDN, 49 GPIO4_B[4]/FLASH_DATA[12], 50 FLASH_DATA[0], 51 FLASH_DATA[4], 52 GPIO4_B[7]/FLASH_DATA[15], 53 GPIO4_B[5]/FLASH_DATA[13], 54 FLASH_CLE, 55 GPIO4_B[1]/FLASH_DATA[9], 56 FLASH_DATA[5], 57 FLASH_CSN0, 58 FLASH_DATA[6], 59 GPIO4_B[0]/FLASH_DATA[8], 60 FLASH_DATA[7], 61 FLASH_DATA[2], 62 FLASH_DATA[3], 63 GPIO0_D[7]/FLASH_CSN6, 64 FLASH_WP, 65 FLASH_WRN, 66 GPIO4_B[6]/FLASH_DATA[14], 67 GPIO0_D[3]/FLASH_CSN2, 68 GPIO0_D[4]/FLASH_CSN3, 69 GPIO0_D[2]/FLASH_CSN1, 70 GPIO0_D[6]/FLASH_CSN5, 71 GPIO1_A[0]/FLASH_CSN7/MDDR_TQ, 72 GPIO0_A[5]/FLASH_DQS, 73 GPIO0_D[5]/FLASH_CSN4, 74 GPIO4_B[2]/FLASH_DATA[10], 75 GPIO4_B[3]/FLASH_DATA[11], 78 GPIO3_B[3]/EMMC_DATA1, 79 GPIO3_B[1]/EMMC_CMD, 80 GPIO3_B[6]/EMMC_DATA4, 81 GPIO3_C[1]/EMMC_DATA7, 82 GPIO3_B[5]/EMMC_DATA3, 83 GPIO3_B[4]/EMMC_DATA2, 84 GPIO3_B[2]/EMMC_DATA0, 85 GPIO3_C[0]/EMMC_DATA6, 86 GPIO3_B[7]/EMMC_DATA5, 88 GPIO3_B[0]/EMMC_CLKOUT, 203 GPIO1_A[5]/EMMC_PWR_EN/PWM3, 246 GPIO6_A[7]
part F pins: 91 GPIO1_C[2]/SDMMC1_CMD, 93 GPIO1_C[7]/SDMMC1_CLKOUT, 95 GPIO1_C[4]/SDMMC1_DATA1, 96 GPIO1_C[3]/SDMMC1_DATA0, 97 GPIO1_C[6]/SDMMC1_DATA3, 98 GPIO1_C[5]/SDMMC1_DATA2, 103 GPIO1_D[3]/SDMMC0_DATA1, 104 GPIO1_D[1]/SDMMC0_CMD, 105 GPIO1_D[5]/SDMMC0_DATA3, 106 GPIO2_A[1]/SDMMC0_DATA7, 107 GPIO1_D[7]/SDMMC0_DATA5, 108 GPIO1_D[2]/SDMMC0_DATA0, 109 GPIO2_A[0]/SDMMC0_DATA6, 110 GPIO1_D[6]/SDMMC0_DATA4, 111 GPIO1_D[4]/SDMMC0_DATA2, 113 GPIO1_D[0]/SDMMC0_CLKOUT, 185 GPIO5_D[7], 193 GPIO2_A[2]/SDMMC0_DETECT_N, 204 GPIO2_A[3]/SDMMC0_WRITE_PRT/PWM2/UART1_SIR_OUT, 208 GPIO5_D[5]/SDMMC0_PWR_EN, 209 GPIO5_D[6]/SDMMC1_PWR_EN
part G pins: 126 GPIO4_C[7]/RMII_RXD0/MII_RXD0, 127 GPIO4_C[3]/RMII_TXD0/MII_TXD0, 128 GPIO4_C[6]/RMII_RXD1/MII_RXD1, 129 GPIO4_C[1]/RMII_TX_EN/MII_TX_EN, 130 GPIO4_C[0]/RMII_CLKOUT/RMII_CLKIN, 131 GPIO4_C[2]/RMII_TXD1/MII_TXD1, 132 GPIO4_C[5]/RMII_CRS_DVALID/MII_RXD_VALID, 133 GPIO4_C[4]/RMII_RX_ERR/MII_RX_ERR, 148 GPIO5_A[3]/MII_TX_CLKIN, 149 GPIO0_A[6]/MII_MD, 189 GPIO0_A[7]/MII_MDCLK, 236 GPIO5_A[2], 248 GPIO6_B[0], 253 GPIO5_A[1], 266 TRST_N, 267 TCK, 268 TDI, 269 TMS, 270 TDO
part H pins: 135 GPIO5_A[7]/HSADC_DATA2, 136 GPIO5_B[5]/HSADC_DATA8/TS_VALID, 137 GPIO5_A[5]/HSADC_DATA0, 138 GPIO5_B[1]/HSADC_DATA4, 139 GPIO5_B[0]/HSADC_DATA3, 140 GPIO5_A[6]/HSADC_DATA1, 141 GPIO5_B[3]/HSADC_DATA6, 142 GPIO5_B[2]/HSADC_DATA5, 143 GPIO5_B[4]/HSADC_DATA7, 144 GPIO5_A[4]/TS_SYNC, 145 GPIO5_B[6]/HSADC_DATA9/TS_FAIL, 146 GPIO5_B[7]/HSADC_CLKOUT/GPS_CLK, 247 GPIO6_B[3]
part I pins: 115 GPIO2_D[1]/I2S0_SCLK/MII_CRS, 116 GPIO4_D[6]/I2S0_LRCK_TX0, 117 GPIO2_D[0]/I2S0_CLK/MII_RX_CLKIN, 118 GPIO2_D[7]/I2S0_SDO3/MII_TXD3, 119 GPIO2_D[4]/I2S0_SDO0/MII_RXD2, 120 GPIO2_D[3]/I2S0_SDI/MII_COL, 121 GPIO4_D[7]/I2S0_LRCK_TX1, 122 GPIO2_D[6]/I2S0_SDO2/MII_TXD2, 123 GPIO2_D[5]/I2S0_SDO1/MII_RXD3, 124 GPIO2_D[2]/I2S0_LRCK_RX/MII_TX_ERR, 165 GPIO4_A[7]/SPDIF_TX, 167 GPIO1_A[3]/EMMC_DETECT_N/SPI1_CSN1, 169 GPIO2_C[6]/SPI1_TXD, 170 GPIO2_C[4]/SPI1_CLK, 171 GPIO2_C[3]/SPI0_RXD, 172 GPIO2_C[2]/SPI0_TXD, 173 GPIO2_C[7]/SPI1_RXD, 174 GPIO2_C[0]/SPI0_CLK, 175 GPIO2_C[1]/SPI0_CSN0, 176 GPIO2_C[5]/SPI1_CSN0, 177 GPIO1_A[6]/I2C1_SDA, 178 GPIO1_A[7]/I2C1_SCL, 192 GPIO1_A[4]/EMMC_WRITE_PRT/SPI0_CSN1, 196 GPIO2_B[7]/I2C0_SCL, 197 GPIO2_B[6]/I2C0_SDA, 205 GPIO5_D[3]/I2C2_SDA, 206 GPIO5_D[4]/I2C2_SCL, 212 GPIO2_B[2]/UART3_SIN, 213 GPIO1_B[6]/UART0_SIN, 214 GPIO2_A[5]/UART1_SOUT, 215 GPIO2_B[1]/UART2_SOUT, 216 GPIO2_B[3]/UART3_SOUT, 217 GPIO2_A[4]/UART1_SIN, 218 GPIO2_B[5]/UART3_RTS_N/I2C3_SCL, 219 GPIO2_B[4]/UART3_CTS_N/I2C3_SDA, 220 GPIO2_B[0]/UART2_SIN, 221 GPIO2_A[6]/UART2_CTS_N, 222 GPIO1_B[7]/UART0_SOUT, 223 GPIO2_A[7]/UART2_RTS_N, 224 GPIO1_C[1]/UART0_RTS_N/SDMMC1_WRITE_PRT, 225 GPIO1_C[0]/UART0_CTS_N/SDMMC1_DETECT_N, 227 GPIO3_A[0]/I2S1_CLK, 228 GPIO3_A[2]/I2S1_LRCK_RX, 229 GPIO3_A[1]/I2S1_SCLK, 230 GPIO3_A[3]/I2S1_SDI, 231 GPIO3_A[4]/I2S1_SDO, 232 GPIO3_A[5]/I2S1_LRCK_TX
part J pins: 23 SARADC_AIN[0], 24 SARADC_AIN[1], 25 SARADC_AIN[2], 26 SARADC_AIN[3], 179 GPIO6_C[3], 180 GPIO6_C[7], 181 GPIO6_C[4], 182 GPIO6_C[0], 183 GPIO4_D[0], 184 GPIO6_C[1], 186 GPIO6_C[2], 188 GPIO6_C[6], 190 GPIO4_D[1], 191 GPIO4_D[5], 194 GPIO4_D[4], 195 GPIO6_C[5], 198 GPIO4_D[2], 207 GPIO4_D[3], 210 GPIO5_D[2]/PWM1/UART1_SIR_IN, 234 GPIO6_A[4], 235 GPIO6_A[3], 237 GPIO6_B[7], 238 GPIO6_A[0], 239 GPIO6_B[6], 241 GPIO6_A[1], 242 GPIO6_A[5], 243 GPIO6_B[4], 244 GPIO6_A[2], 245 GPIO6_A[6], 249 GPIO5_A[0], 250 GPIO6_B[2], 251 GPIO6_B[1], 252 GPIO0_A[1], 254 GPIO0_A[0], 255 GPIO0_A[2], 256 GPIO0_A[4], 257 GPIO0_A[3], 258 GPIO4_A[3], 259 GPIO4_A[0], 260 GPIO4_A[1], 261 GPIO4_A[2], 262 GPIO4_A[4]
part K pins: 1 GND, 2 GND, 21 GND, 22 GND, 27 GND, 28 GND, 31 GND, 34 GND, 37 GND, 40 GND, 42 GND, 44 GND, 76 GND, 77 GND, 87 GND, 89 GND, 90 GND, 92 GND, 94 GND, 99 GND, 100 GND, 101 GND, 102 GND, 112 GND, 114 GND, 125 GND, 134 GND, 147 GND, 164 GND, 168 GND, 199 GND, 200 GND, 201 GND, 202 GND, 226 GND, 233 GND, 263 GND, 265 GND, 275 TopBoard_DET0, 276 TopBoard_DET1, 277 GND, 278 VB, 279 GND, 280 VCC18, 281 GND, 282 VCC25, 283 GND, 284 VCCA, 285 GND, 286 VCC, 287 GND, 288 GND, 289 VDD, 290 VDD, 291 VDD, 292 VDD, 293 GND, 294 GND, 295 VCCDR, 296 VCCDR, 297 VCCDR, 298 VCCDR, 299 GND, 300 GND, 301 GND, 302 GND, 303 GND, 304 GND, 306 GND, 308 GND, 310 GND, 312 GND, 314 GND, 316 GND, 318 GND, 320 GND, 322 GND, 324 GND, 326 GND, 328 GND, 330 GND, 332 GND, 334 GND, 336 GND, 338 GND, 340 GND, 342 GND, 344 GND, 346 GND, 348 GND, 350 GND, 352 GND, 354 GND, 356 GND, 358 GND, 360 GND, 361 GND, 362 GND, 375 GND, 377 GND, 379 GND, 381 GND, 383 GND, 384 GND, 385 GND, 399 GND, 400 GND

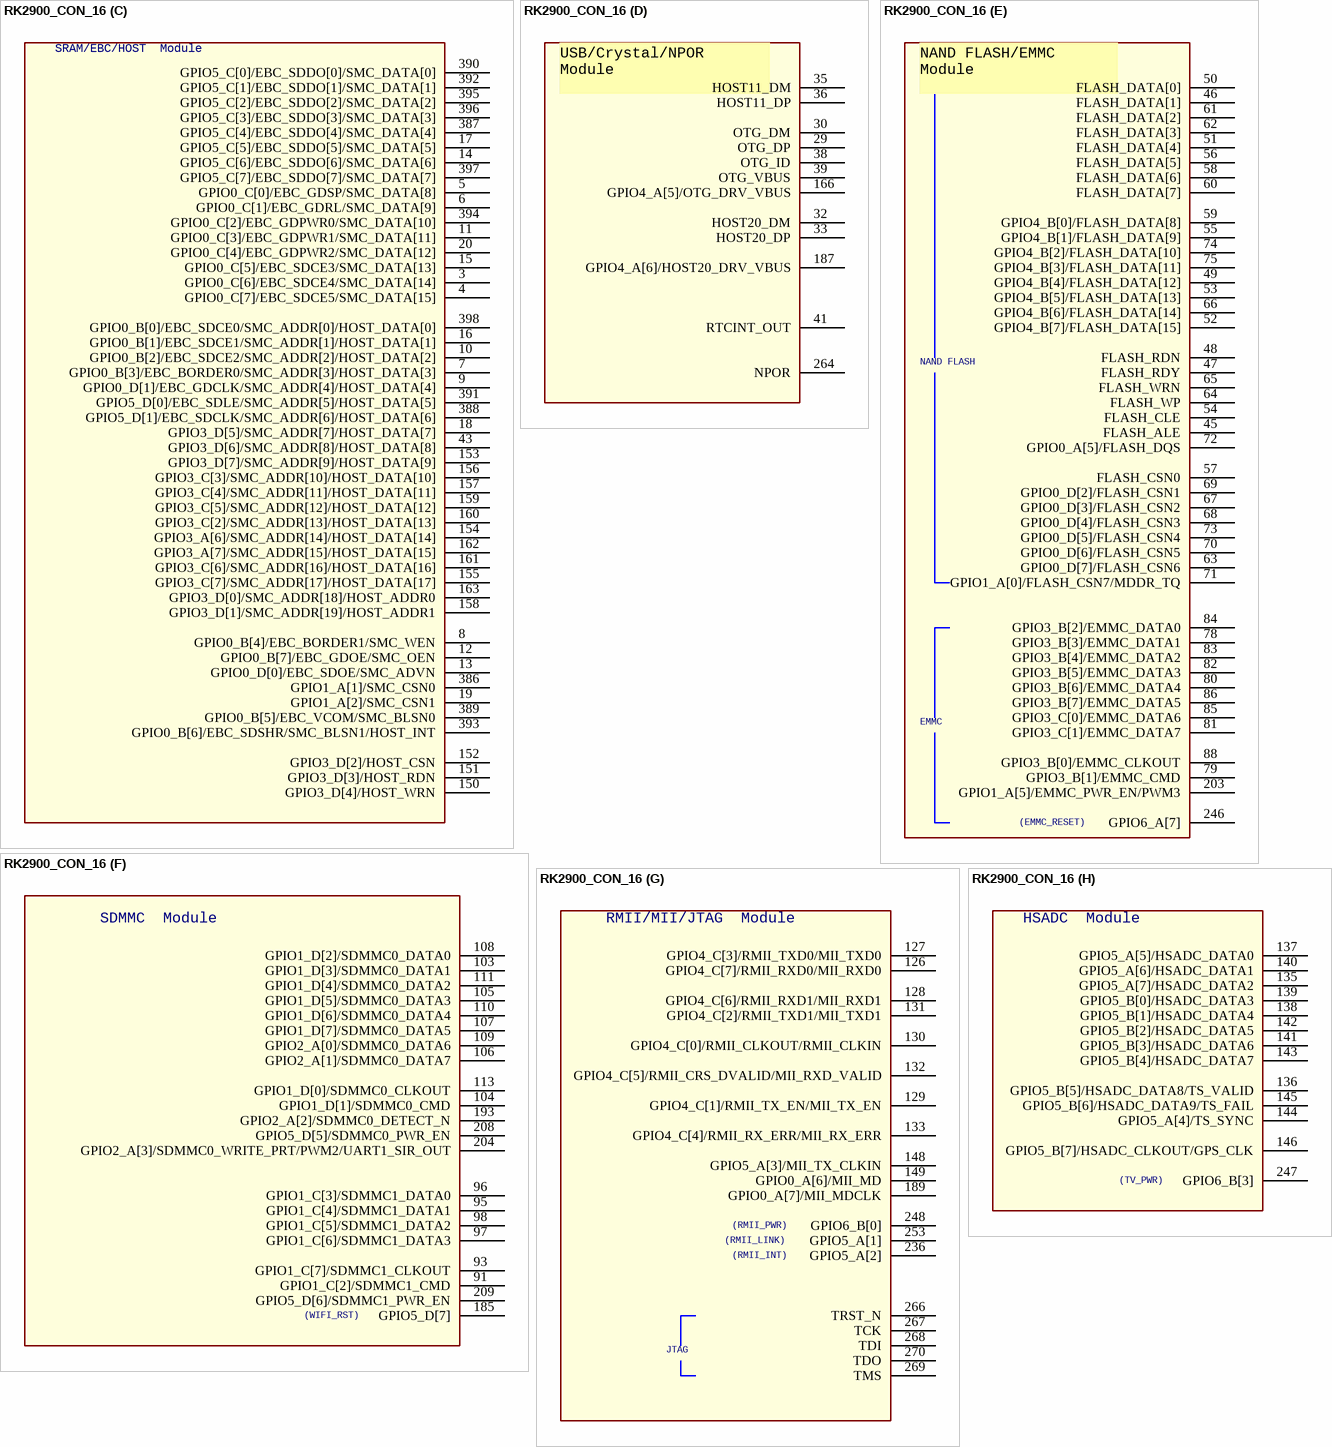
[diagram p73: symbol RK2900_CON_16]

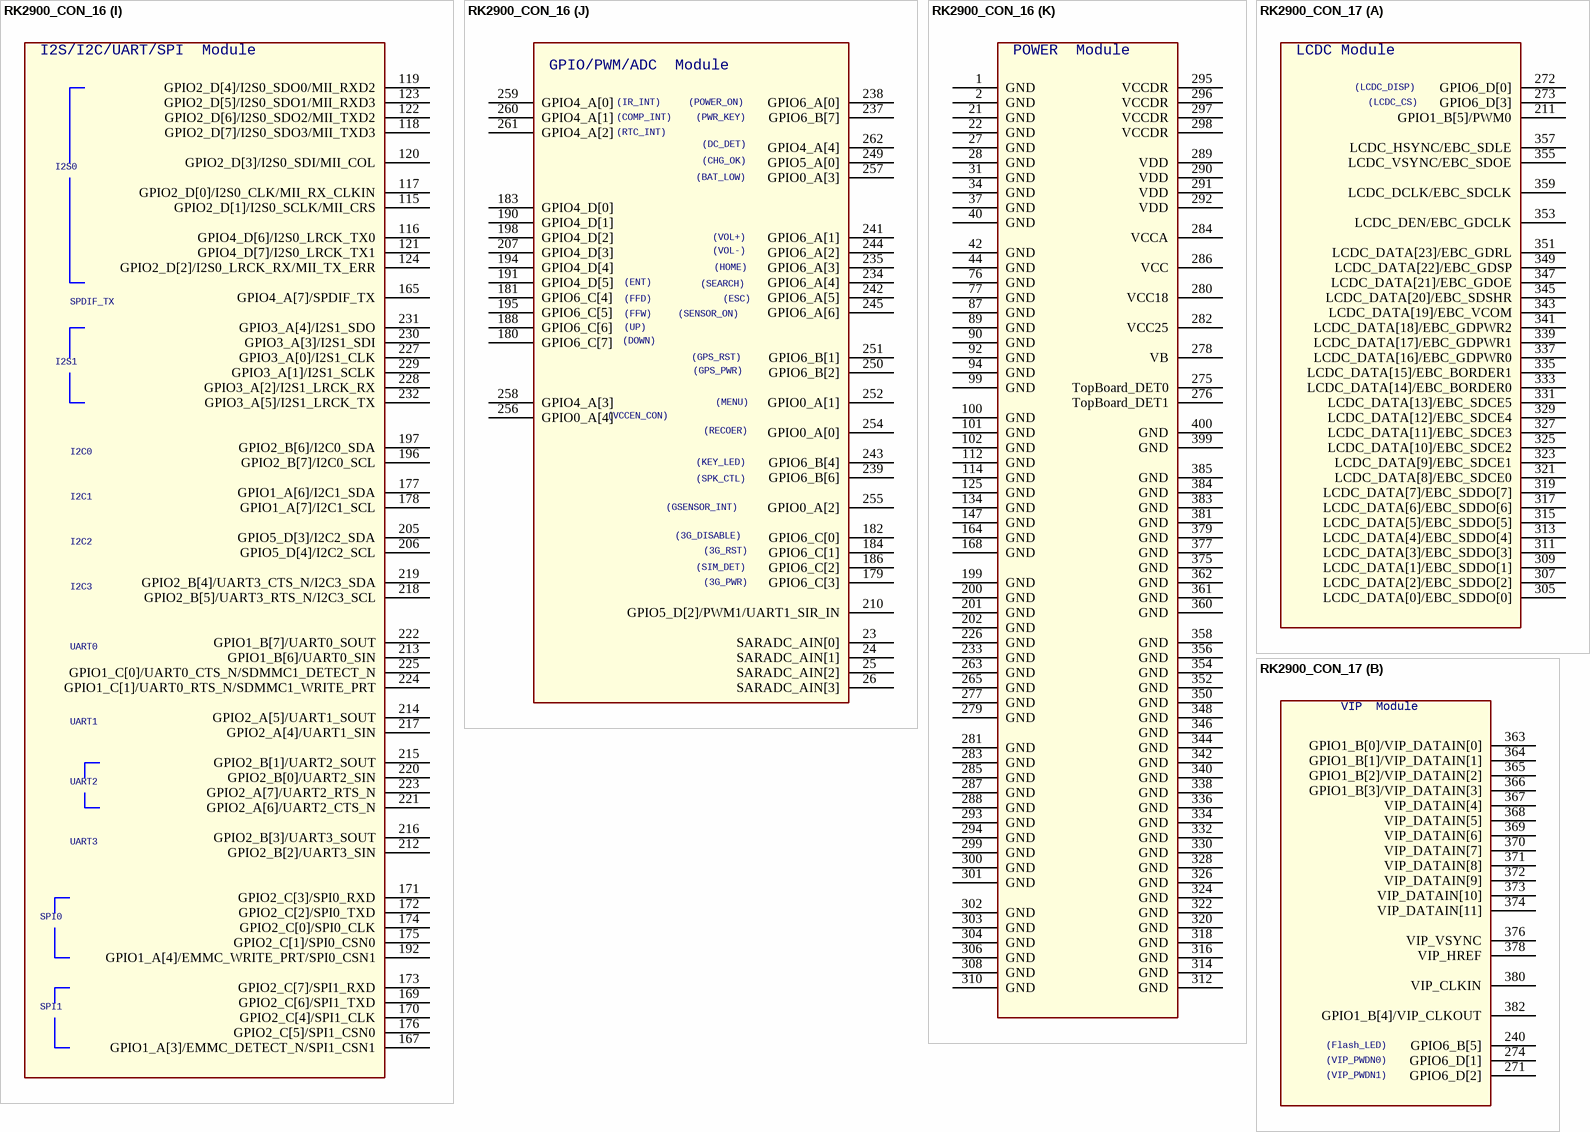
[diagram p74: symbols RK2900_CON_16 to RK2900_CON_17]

## RK2900_CON_16
designator U?
Altium-Right: 160; Altium-Bottom: 390; Altium-Right1: 140; Altium-Bottom1: 270; Altium-Right2: 280; Altium-Bottom2: 520; Altium-Right3: 170; Altium-Bottom3: 240; Altium-Right4: 190; Altium-Bottom4: 530; Altium-Right5: 290; Altium-Bottom5: 300; Altium-Right6: 220; Altium-Bottom6: 340; Altium-Right7: 180; Altium-Bottom7: 200; Altium-Bottom8: 690; Altium-Right9: 210; Altium-Bottom9: 440; Altium-Right10: 120; Altium-Bottom10: 650
footprint RK2900_TOP
part A pins: 211 GPIO1_B[5]/PWM0, 272 GPIO6_D[0], 273 GPIO6_D[3], 305 LCDC_DATA[0]/EBC_SDDO[0], 307 LCDC_DATA[2]/EBC_SDDO[2], 309 LCDC_DATA[1]/EBC_SDDO[1], 311 LCDC_DATA[3]/EBC_SDDO[3], 313 LCDC_DATA[4]/EBC_SDDO[4], 315 LCDC_DATA[5]/EBC_SDDO[5], 317 LCDC_DATA[6]/EBC_SDDO[6], 319 LCDC_DATA[7]/EBC_SDDO[7], 321 LCDC_DATA[8]/EBC_SDCE0, 323 LCDC_DATA[9]/EBC_SDCE1, 325 LCDC_DATA[10]/EBC_SDCE2, 327 LCDC_DATA[11]/EBC_SDCE3, 329 LCDC_DATA[12]/EBC_SDCE4, 331 LCDC_DATA[13]/EBC_SDCE5, 333 LCDC_DATA[14]/EBC_BORDER0, 335 LCDC_DATA[15]/EBC_BORDER1, 337 LCDC_DATA[16]/EBC_GDPWR0, 339 LCDC_DATA[17]/EBC_GDPWR1, 341 LCDC_DATA[18]/EBC_GDPWR2, 343 LCDC_DATA[19]/EBC_VCOM, 345 LCDC_DATA[20]/EBC_SDSHR, 347 LCDC_DATA[21]/EBC_GDOE, 349 LCDC_DATA[22]/EBC_GDSP, 351 LCDC_DATA[23]/EBC_GDRL, 353 LCDC_DEN/EBC_GDCLK, 355 LCDC_VSYNC/EBC_SDOE, 357 LCDC_HSYNC/EBC_SDLE, 359 LCDC_DCLK/EBC_SDCLK
part B pins: 240 GPIO6_B[5], 271 GPIO6_D[2], 274 GPIO6_D[1], 363 GPIO1_B[0]/VIP_DATAIN[0], 364 GPIO1_B[1]/VIP_DATAIN[1], 365 GPIO1_B[2]/VIP_DATAIN[2], 366 GPIO1_B[3]/VIP_DATAIN[3], 367 VIP_DATAIN[4], 368 VIP_DATAIN[5], 369 VIP_DATAIN[6], 370 VIP_DATAIN[7], 371 VIP_DATAIN[8], 372 VIP_DATAIN[9], 373 VIP_DATAIN[10], 374 VIP_DATAIN[11], 376 VIP_VSYNC, 378 VIP_HREF, 380 VIP_CLKIN, 382 GPIO1_B[4]/VIP_CLKOUT
part C pins: 3 GPIO0_C[6]/EBC_SDCE4/SMC_DATA[14], 4 GPIO0_C[7]/EBC_SDCE5/SMC_DATA[15], 5 GPIO0_C[0]/EBC_GDSP/SMC_DATA[8], 6 GPIO0_C[1]/EBC_GDRL/SMC_DATA[9], 7 GPIO0_B[3]/EBC_BORDER0/SMC_ADDR[3]/HOST_DATA[3], 8 GPIO0_B[4]/EBC_BORDER1/SMC_WEN, 9 GPIO0_D[1]/EBC_GDCLK/SMC_ADDR[4]/HOST_DATA[4], 10 GPIO0_B[2]/EBC_SDCE2/SMC_ADDR[2]/HOST_DATA[2], 11 GPIO0_C[3]/EBC_GDPWR1/SMC_DATA[11], 12 GPIO0_B[7]/EBC_GDOE/SMC_OEN, 13 GPIO0_D[0]/EBC_SDOE/SMC_ADVN, 14 GPIO5_C[6]/EBC_SDDO[6]/SMC_DATA[6], 15 GPIO0_C[5]/EBC_SDCE3/SMC_DATA[13], 16 GPIO0_B[1]/EBC_SDCE1/SMC_ADDR[1]/HOST_DATA[1], 17 GPIO5_C[5]/EBC_SDDO[5]/SMC_DATA[5], 18 GPIO3_D[5]/SMC_ADDR[7]/HOST_DATA[7], 19 GPIO1_A[2]/SMC_CSN1, 20 GPIO0_C[4]/EBC_GDPWR2/SMC_DATA[12], 43 GPIO3_D[6]/SMC_ADDR[8]/HOST_DATA[8], 150 GPIO3_D[4]/HOST_WRN, 151 GPIO3_D[3]/HOST_RDN, 152 GPIO3_D[2]/HOST_CSN, 153 GPIO3_D[7]/SMC_ADDR[9]/HOST_DATA[9], 154 GPIO3_A[6]/SMC_ADDR[14]/HOST_DATA[14], 155 GPIO3_C[7]/SMC_ADDR[17]/HOST_DATA[17], 156 GPIO3_C[3]/SMC_ADDR[10]/HOST_DATA[10], 157 GPIO3_C[4]/SMC_ADDR[11]/HOST_DATA[11], 158 GPIO3_D[1]/SMC_ADDR[19]/HOST_ADDR1, 159 GPIO3_C[5]/SMC_ADDR[12]/HOST_DATA[12], 160 GPIO3_C[2]/SMC_ADDR[13]/HOST_DATA[13], 161 GPIO3_C[6]/SMC_ADDR[16]/HOST_DATA[16], 162 GPIO3_A[7]/SMC_ADDR[15]/HOST_DATA[15], 163 GPIO3_D[0]/SMC_ADDR[18]/HOST_ADDR0, 386 GPIO1_A[1]/SMC_CSN0, 387 GPIO5_C[4]/EBC_SDDO[4]/SMC_DATA[4], 388 GPIO5_D[1]/EBC_SDCLK/SMC_ADDR[6]/HOST_DATA[6], 389 GPIO0_B[5]/EBC_VCOM/SMC_BLSN0, 390 GPIO5_C[0]/EBC_SDDO[0]/SMC_DATA[0], 391 GPIO5_D[0]/EBC_SDLE/SMC_ADDR[5]/HOST_DATA[5], 392 GPIO5_C[1]/EBC_SDDO[1]/SMC_DATA[1], 393 GPIO0_B[6]/EBC_SDSHR/SMC_BLSN1/HOST_INT, 394 GPIO0_C[2]/EBC_GDPWR0/SMC_DATA[10], 395 GPIO5_C[2]/EBC_SDDO[2]/SMC_DATA[2], 396 GPIO5_C[3]/EBC_SDDO[3]/SMC_DATA[3], 397 GPIO5_C[7]/EBC_SDDO[7]/SMC_DATA[7], 398 GPIO0_B[0]/EBC_SDCE0/SMC_ADDR[0]/HOST_DATA[0]
part D pins: 29 OTG_DP, 30 OTG_DM, 32 HOST20_DM, 33 HOST20_DP, 35 HOST11_DM, 36 HOST11_DP, 38 OTG_ID, 39 OTG_VBUS, 41 RTCINT_OUT, 166 GPIO4_A[5]/OTG_DRV_VBUS, 187 GPIO4_A[6]/HOST20_DRV_VBUS, 264 NPOR
part E pins: 45 FLASH_ALE, 46 FLASH_DATA[1], 47 FLASH_RDY, 48 FLASH_RDN, 49 GPIO4_B[4]/FLASH_DATA[12], 50 FLASH_DATA[0], 51 FLASH_DATA[4], 52 GPIO4_B[7]/FLASH_DATA[15], 53 GPIO4_B[5]/FLASH_DATA[13], 54 FLASH_CLE, 55 GPIO4_B[1]/FLASH_DATA[9], 56 FLASH_DATA[5], 57 FLASH_CSN0, 58 FLASH_DATA[6], 59 GPIO4_B[0]/FLASH_DATA[8], 60 FLASH_DATA[7], 61 FLASH_DATA[2], 62 FLASH_DATA[3], 63 GPIO0_D[7]/FLASH_CSN6, 64 FLASH_WP, 65 FLASH_WRN, 66 GPIO4_B[6]/FLASH_DATA[14], 67 GPIO0_D[3]/FLASH_CSN2, 68 GPIO0_D[4]/FLASH_CSN3, 69 GPIO0_D[2]/FLASH_CSN1, 70 GPIO0_D[6]/FLASH_CSN5, 71 GPIO1_A[0]/FLASH_CSN7/MDDR_TQ, 72 GPIO0_A[5]/FLASH_DQS, 73 GPIO0_D[5]/FLASH_CSN4, 74 GPIO4_B[2]/FLASH_DATA[10], 75 GPIO4_B[3]/FLASH_DATA[11], 78 GPIO3_B[3]/EMMC_DATA1, 79 GPIO3_B[1]/EMMC_CMD, 80 GPIO3_B[6]/EMMC_DATA4, 81 GPIO3_C[1]/EMMC_DATA7, 82 GPIO3_B[5]/EMMC_DATA3, 83 GPIO3_B[4]/EMMC_DATA2, 84 GPIO3_B[2]/EMMC_DATA0, 85 GPIO3_C[0]/EMMC_DATA6, 86 GPIO3_B[7]/EMMC_DATA5, 88 GPIO3_B[0]/EMMC_CLKOUT, 203 GPIO1_A[5]/EMMC_PWR_EN/PWM3, 246 GPIO6_A[7]
part F pins: 91 GPIO1_C[2]/SDMMC1_CMD, 93 GPIO1_C[7]/SDMMC1_CLKOUT, 95 GPIO1_C[4]/SDMMC1_DATA1, 96 GPIO1_C[3]/SDMMC1_DATA0, 97 GPIO1_C[6]/SDMMC1_DATA3, 98 GPIO1_C[5]/SDMMC1_DATA2, 103 GPIO1_D[3]/SDMMC0_DATA1, 104 GPIO1_D[1]/SDMMC0_CMD, 105 GPIO1_D[5]/SDMMC0_DATA3, 106 GPIO2_A[1]/SDMMC0_DATA7, 107 GPIO1_D[7]/SDMMC0_DATA5, 108 GPIO1_D[2]/SDMMC0_DATA0, 109 GPIO2_A[0]/SDMMC0_DATA6, 110 GPIO1_D[6]/SDMMC0_DATA4, 111 GPIO1_D[4]/SDMMC0_DATA2, 113 GPIO1_D[0]/SDMMC0_CLKOUT, 185 GPIO5_D[7], 193 GPIO2_A[2]/SDMMC0_DETECT_N, 204 GPIO2_A[3]/SDMMC0_WRITE_PRT/PWM2/UART1_SIR_OUT, 208 GPIO5_D[5]/SDMMC0_PWR_EN, 209 GPIO5_D[6]/SDMMC1_PWR_EN
part G pins: 126 GPIO4_C[7]/RMII_RXD0/MII_RXD0, 127 GPIO4_C[3]/RMII_TXD0/MII_TXD0, 128 GPIO4_C[6]/RMII_RXD1/MII_RXD1, 129 GPIO4_C[1]/RMII_TX_EN/MII_TX_EN, 130 GPIO4_C[0]/RMII_CLKOUT/RMII_CLKIN, 131 GPIO4_C[2]/RMII_TXD1/MII_TXD1, 132 GPIO4_C[5]/RMII_CRS_DVALID/MII_RXD_VALID, 133 GPIO4_C[4]/RMII_RX_ERR/MII_RX_ERR, 148 GPIO5_A[3]/MII_TX_CLKIN, 149 GPIO0_A[6]/MII_MD, 189 GPIO0_A[7]/MII_MDCLK, 236 GPIO5_A[2], 248 GPIO6_B[0], 253 GPIO5_A[1], 266 TRST_N, 267 TCK, 268 TDI, 269 TMS, 270 TDO
part H pins: 135 GPIO5_A[7]/HSADC_DATA2, 136 GPIO5_B[5]/HSADC_DATA8/TS_VALID, 137 GPIO5_A[5]/HSADC_DATA0, 138 GPIO5_B[1]/HSADC_DATA4, 139 GPIO5_B[0]/HSADC_DATA3, 140 GPIO5_A[6]/HSADC_DATA1, 141 GPIO5_B[3]/HSADC_DATA6, 142 GPIO5_B[2]/HSADC_DATA5, 143 GPIO5_B[4]/HSADC_DATA7, 144 GPIO5_A[4]/TS_SYNC, 145 GPIO5_B[6]/HSADC_DATA9/TS_FAIL, 146 GPIO5_B[7]/HSADC_CLKOUT/GPS_CLK, 247 GPIO6_B[3]
part I pins: 115 GPIO2_D[1]/I2S0_SCLK/MII_CRS, 116 GPIO4_D[6]/I2S0_LRCK_TX0, 117 GPIO2_D[0]/I2S0_CLK/MII_RX_CLKIN, 118 GPIO2_D[7]/I2S0_SDO3/MII_TXD3, 119 GPIO2_D[4]/I2S0_SDO0/MII_RXD2, 120 GPIO2_D[3]/I2S0_SDI/MII_COL, 121 GPIO4_D[7]/I2S0_LRCK_TX1, 122 GPIO2_D[6]/I2S0_SDO2/MII_TXD2, 123 GPIO2_D[5]/I2S0_SDO1/MII_RXD3, 124 GPIO2_D[2]/I2S0_LRCK_RX/MII_TX_ERR, 165 GPIO4_A[7]/SPDIF_TX, 167 GPIO1_A[3]/EMMC_DETECT_N/SPI1_CSN1, 169 GPIO2_C[6]/SPI1_TXD, 170 GPIO2_C[4]/SPI1_CLK, 171 GPIO2_C[3]/SPI0_RXD, 172 GPIO2_C[2]/SPI0_TXD, 173 GPIO2_C[7]/SPI1_RXD, 174 GPIO2_C[0]/SPI0_CLK, 175 GPIO2_C[1]/SPI0_CSN0, 176 GPIO2_C[5]/SPI1_CSN0, 177 GPIO1_A[6]/I2C1_SDA, 178 GPIO1_A[7]/I2C1_SCL, 192 GPIO1_A[4]/EMMC_WRITE_PRT/SPI0_CSN1, 196 GPIO2_B[7]/I2C0_SCL, 197 GPIO2_B[6]/I2C0_SDA, 205 GPIO5_D[3]/I2C2_SDA, 206 GPIO5_D[4]/I2C2_SCL, 212 GPIO2_B[2]/UART3_SIN, 213 GPIO1_B[6]/UART0_SIN, 214 GPIO2_A[5]/UART1_SOUT, 215 GPIO2_B[1]/UART2_SOUT, 216 GPIO2_B[3]/UART3_SOUT, 217 GPIO2_A[4]/UART1_SIN, 218 GPIO2_B[5]/UART3_RTS_N/I2C3_SCL, 219 GPIO2_B[4]/UART3_CTS_N/I2C3_SDA, 220 GPIO2_B[0]/UART2_SIN, 221 GPIO2_A[6]/UART2_CTS_N, 222 GPIO1_B[7]/UART0_SOUT, 223 GPIO2_A[7]/UART2_RTS_N, 224 GPIO1_C[1]/UART0_RTS_N/SDMMC1_WRITE_PRT, 225 GPIO1_C[0]/UART0_CTS_N/SDMMC1_DETECT_N, 227 GPIO3_A[0]/I2S1_CLK, 228 GPIO3_A[2]/I2S1_LRCK_RX, 229 GPIO3_A[1]/I2S1_SCLK, 230 GPIO3_A[3]/I2S1_SDI, 231 GPIO3_A[4]/I2S1_SDO, 232 GPIO3_A[5]/I2S1_LRCK_TX
part J pins: 23 SARADC_AIN[0], 24 SARADC_AIN[1], 25 SARADC_AIN[2], 26 SARADC_AIN[3], 179 GPIO6_C[3], 180 GPIO6_C[7], 181 GPIO6_C[4], 182 GPIO6_C[0], 183 GPIO4_D[0], 184 GPIO6_C[1], 186 GPIO6_C[2], 188 GPIO6_C[6], 190 GPIO4_D[1], 191 GPIO4_D[5], 194 GPIO4_D[4], 195 GPIO6_C[5], 198 GPIO4_D[2], 207 GPIO4_D[3], 210 GPIO5_D[2]/PWM1/UART1_SIR_IN, 234 GPIO6_A[4], 235 GPIO6_A[3], 237 GPIO6_B[7], 238 GPIO6_A[0], 239 GPIO6_B[6], 241 GPIO6_A[1], 242 GPIO6_A[5], 243 GPIO6_B[4], 244 GPIO6_A[2], 245 GPIO6_A[6], 249 GPIO5_A[0], 250 GPIO6_B[2], 251 GPIO6_B[1], 252 GPIO0_A[1], 254 GPIO0_A[0], 255 GPIO0_A[2], 256 GPIO0_A[4], 257 GPIO0_A[3], 258 GPIO4_A[3], 259 GPIO4_A[0], 260 GPIO4_A[1], 261 GPIO4_A[2], 262 GPIO4_A[4]
part K pins: 1 GND, 2 GND, 21 GND, 22 GND, 27 GND, 28 GND, 31 GND, 34 GND, 37 GND, 40 GND, 42 GND, 44 GND, 76 GND, 77 GND, 87 GND, 89 GND, 90 GND, 92 GND, 94 GND, 99 GND, 100 GND, 101 GND, 102 GND, 112 GND, 114 GND, 125 GND, 134 GND, 147 GND, 164 GND, 168 GND, 199 GND, 200 GND, 201 GND, 202 GND, 226 GND, 233 GND, 263 GND, 265 GND, 275 TopBoard_DET0, 276 TopBoard_DET1, 277 GND, 278 VB, 279 GND, 280 VCC18, 281 GND, 282 VCC25, 283 GND, 284 VCCA, 285 GND, 286 VCC, 287 GND, 288 GND, 289 VDD, 290 VDD, 291 VDD, 292 VDD, 293 GND, 294 GND, 295 VCCDR, 296 VCCDR, 297 VCCDR, 298 VCCDR, 299 GND, 300 GND, 301 GND, 302 GND, 303 GND, 304 GND, 306 GND, 308 GND, 310 GND, 312 GND, 314 GND, 316 GND, 318 GND, 320 GND, 322 GND, 324 GND, 326 GND, 328 GND, 330 GND, 332 GND, 334 GND, 336 GND, 338 GND, 340 GND, 342 GND, 344 GND, 346 GND, 348 GND, 350 GND, 352 GND, 354 GND, 356 GND, 358 GND, 360 GND, 361 GND, 362 GND, 375 GND, 377 GND, 379 GND, 381 GND, 383 GND, 384 GND, 385 GND, 399 GND, 400 GND

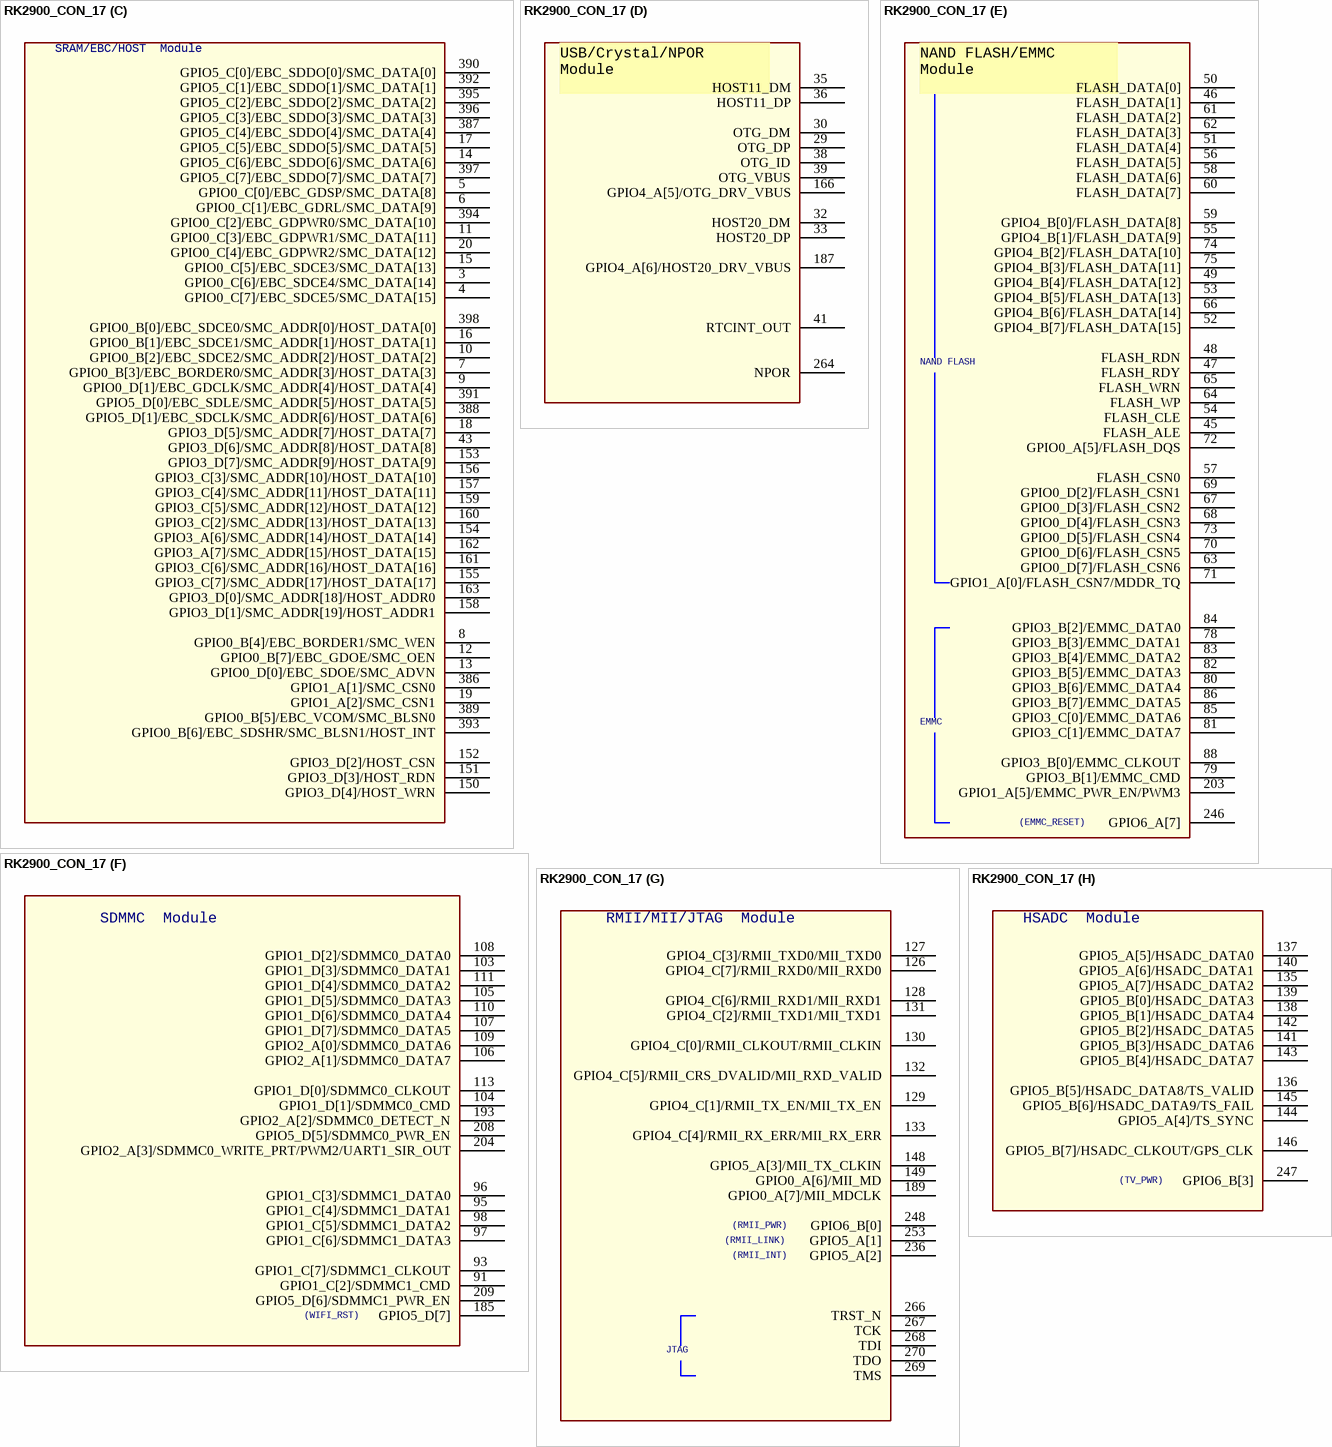
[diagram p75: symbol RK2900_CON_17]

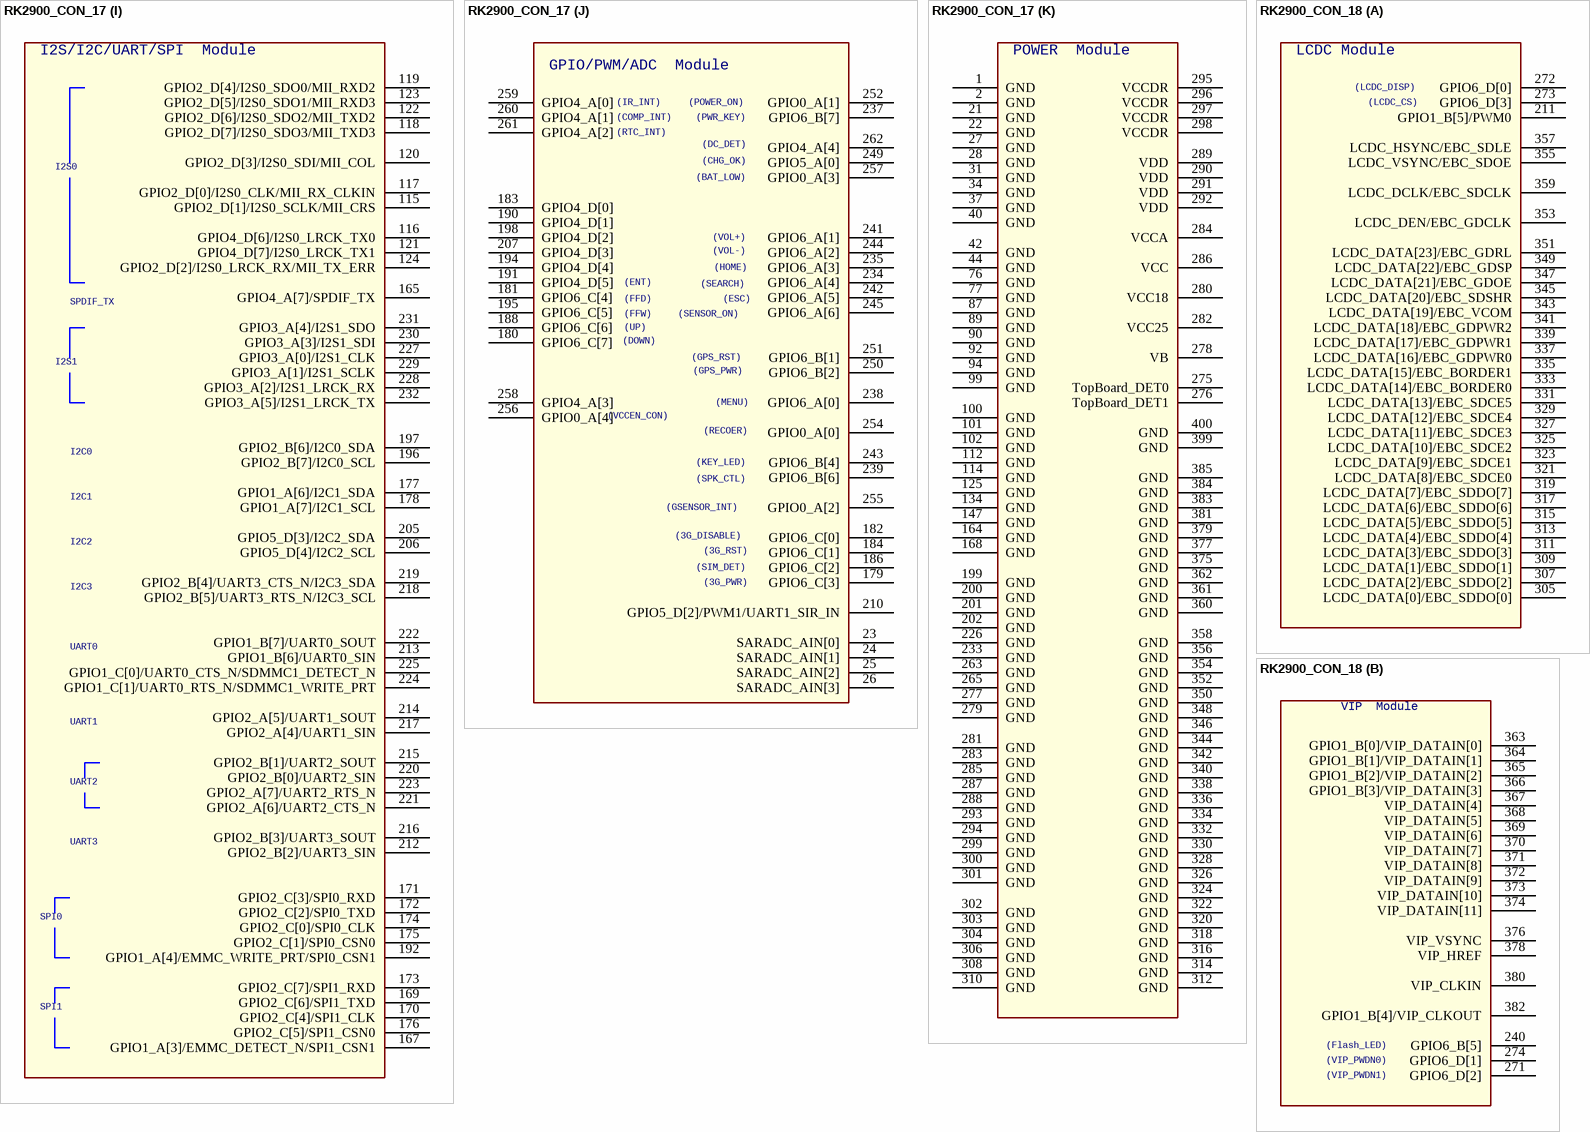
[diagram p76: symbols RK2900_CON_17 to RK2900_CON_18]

## RK2900_CON_17
designator U?
Altium-Right: 160; Altium-Bottom: 390; Altium-Right1: 140; Altium-Bottom1: 270; Altium-Right2: 280; Altium-Bottom2: 520; Altium-Right3: 170; Altium-Bottom3: 240; Altium-Right4: 190; Altium-Bottom4: 530; Altium-Right5: 290; Altium-Bottom5: 300; Altium-Right6: 220; Altium-Bottom6: 340; Altium-Right7: 180; Altium-Bottom7: 200; Altium-Bottom8: 690; Altium-Right9: 210; Altium-Bottom9: 440; Altium-Right10: 120; Altium-Bottom10: 650
footprint RK2900_TOP
part A pins: 211 GPIO1_B[5]/PWM0, 272 GPIO6_D[0], 273 GPIO6_D[3], 305 LCDC_DATA[0]/EBC_SDDO[0], 307 LCDC_DATA[2]/EBC_SDDO[2], 309 LCDC_DATA[1]/EBC_SDDO[1], 311 LCDC_DATA[3]/EBC_SDDO[3], 313 LCDC_DATA[4]/EBC_SDDO[4], 315 LCDC_DATA[5]/EBC_SDDO[5], 317 LCDC_DATA[6]/EBC_SDDO[6], 319 LCDC_DATA[7]/EBC_SDDO[7], 321 LCDC_DATA[8]/EBC_SDCE0, 323 LCDC_DATA[9]/EBC_SDCE1, 325 LCDC_DATA[10]/EBC_SDCE2, 327 LCDC_DATA[11]/EBC_SDCE3, 329 LCDC_DATA[12]/EBC_SDCE4, 331 LCDC_DATA[13]/EBC_SDCE5, 333 LCDC_DATA[14]/EBC_BORDER0, 335 LCDC_DATA[15]/EBC_BORDER1, 337 LCDC_DATA[16]/EBC_GDPWR0, 339 LCDC_DATA[17]/EBC_GDPWR1, 341 LCDC_DATA[18]/EBC_GDPWR2, 343 LCDC_DATA[19]/EBC_VCOM, 345 LCDC_DATA[20]/EBC_SDSHR, 347 LCDC_DATA[21]/EBC_GDOE, 349 LCDC_DATA[22]/EBC_GDSP, 351 LCDC_DATA[23]/EBC_GDRL, 353 LCDC_DEN/EBC_GDCLK, 355 LCDC_VSYNC/EBC_SDOE, 357 LCDC_HSYNC/EBC_SDLE, 359 LCDC_DCLK/EBC_SDCLK
part B pins: 240 GPIO6_B[5], 271 GPIO6_D[2], 274 GPIO6_D[1], 363 GPIO1_B[0]/VIP_DATAIN[0], 364 GPIO1_B[1]/VIP_DATAIN[1], 365 GPIO1_B[2]/VIP_DATAIN[2], 366 GPIO1_B[3]/VIP_DATAIN[3], 367 VIP_DATAIN[4], 368 VIP_DATAIN[5], 369 VIP_DATAIN[6], 370 VIP_DATAIN[7], 371 VIP_DATAIN[8], 372 VIP_DATAIN[9], 373 VIP_DATAIN[10], 374 VIP_DATAIN[11], 376 VIP_VSYNC, 378 VIP_HREF, 380 VIP_CLKIN, 382 GPIO1_B[4]/VIP_CLKOUT
part C pins: 3 GPIO0_C[6]/EBC_SDCE4/SMC_DATA[14], 4 GPIO0_C[7]/EBC_SDCE5/SMC_DATA[15], 5 GPIO0_C[0]/EBC_GDSP/SMC_DATA[8], 6 GPIO0_C[1]/EBC_GDRL/SMC_DATA[9], 7 GPIO0_B[3]/EBC_BORDER0/SMC_ADDR[3]/HOST_DATA[3], 8 GPIO0_B[4]/EBC_BORDER1/SMC_WEN, 9 GPIO0_D[1]/EBC_GDCLK/SMC_ADDR[4]/HOST_DATA[4], 10 GPIO0_B[2]/EBC_SDCE2/SMC_ADDR[2]/HOST_DATA[2], 11 GPIO0_C[3]/EBC_GDPWR1/SMC_DATA[11], 12 GPIO0_B[7]/EBC_GDOE/SMC_OEN, 13 GPIO0_D[0]/EBC_SDOE/SMC_ADVN, 14 GPIO5_C[6]/EBC_SDDO[6]/SMC_DATA[6], 15 GPIO0_C[5]/EBC_SDCE3/SMC_DATA[13], 16 GPIO0_B[1]/EBC_SDCE1/SMC_ADDR[1]/HOST_DATA[1], 17 GPIO5_C[5]/EBC_SDDO[5]/SMC_DATA[5], 18 GPIO3_D[5]/SMC_ADDR[7]/HOST_DATA[7], 19 GPIO1_A[2]/SMC_CSN1, 20 GPIO0_C[4]/EBC_GDPWR2/SMC_DATA[12], 43 GPIO3_D[6]/SMC_ADDR[8]/HOST_DATA[8], 150 GPIO3_D[4]/HOST_WRN, 151 GPIO3_D[3]/HOST_RDN, 152 GPIO3_D[2]/HOST_CSN, 153 GPIO3_D[7]/SMC_ADDR[9]/HOST_DATA[9], 154 GPIO3_A[6]/SMC_ADDR[14]/HOST_DATA[14], 155 GPIO3_C[7]/SMC_ADDR[17]/HOST_DATA[17], 156 GPIO3_C[3]/SMC_ADDR[10]/HOST_DATA[10], 157 GPIO3_C[4]/SMC_ADDR[11]/HOST_DATA[11], 158 GPIO3_D[1]/SMC_ADDR[19]/HOST_ADDR1, 159 GPIO3_C[5]/SMC_ADDR[12]/HOST_DATA[12], 160 GPIO3_C[2]/SMC_ADDR[13]/HOST_DATA[13], 161 GPIO3_C[6]/SMC_ADDR[16]/HOST_DATA[16], 162 GPIO3_A[7]/SMC_ADDR[15]/HOST_DATA[15], 163 GPIO3_D[0]/SMC_ADDR[18]/HOST_ADDR0, 386 GPIO1_A[1]/SMC_CSN0, 387 GPIO5_C[4]/EBC_SDDO[4]/SMC_DATA[4], 388 GPIO5_D[1]/EBC_SDCLK/SMC_ADDR[6]/HOST_DATA[6], 389 GPIO0_B[5]/EBC_VCOM/SMC_BLSN0, 390 GPIO5_C[0]/EBC_SDDO[0]/SMC_DATA[0], 391 GPIO5_D[0]/EBC_SDLE/SMC_ADDR[5]/HOST_DATA[5], 392 GPIO5_C[1]/EBC_SDDO[1]/SMC_DATA[1], 393 GPIO0_B[6]/EBC_SDSHR/SMC_BLSN1/HOST_INT, 394 GPIO0_C[2]/EBC_GDPWR0/SMC_DATA[10], 395 GPIO5_C[2]/EBC_SDDO[2]/SMC_DATA[2], 396 GPIO5_C[3]/EBC_SDDO[3]/SMC_DATA[3], 397 GPIO5_C[7]/EBC_SDDO[7]/SMC_DATA[7], 398 GPIO0_B[0]/EBC_SDCE0/SMC_ADDR[0]/HOST_DATA[0]
part D pins: 29 OTG_DP, 30 OTG_DM, 32 HOST20_DM, 33 HOST20_DP, 35 HOST11_DM, 36 HOST11_DP, 38 OTG_ID, 39 OTG_VBUS, 41 RTCINT_OUT, 166 GPIO4_A[5]/OTG_DRV_VBUS, 187 GPIO4_A[6]/HOST20_DRV_VBUS, 264 NPOR
part E pins: 45 FLASH_ALE, 46 FLASH_DATA[1], 47 FLASH_RDY, 48 FLASH_RDN, 49 GPIO4_B[4]/FLASH_DATA[12], 50 FLASH_DATA[0], 51 FLASH_DATA[4], 52 GPIO4_B[7]/FLASH_DATA[15], 53 GPIO4_B[5]/FLASH_DATA[13], 54 FLASH_CLE, 55 GPIO4_B[1]/FLASH_DATA[9], 56 FLASH_DATA[5], 57 FLASH_CSN0, 58 FLASH_DATA[6], 59 GPIO4_B[0]/FLASH_DATA[8], 60 FLASH_DATA[7], 61 FLASH_DATA[2], 62 FLASH_DATA[3], 63 GPIO0_D[7]/FLASH_CSN6, 64 FLASH_WP, 65 FLASH_WRN, 66 GPIO4_B[6]/FLASH_DATA[14], 67 GPIO0_D[3]/FLASH_CSN2, 68 GPIO0_D[4]/FLASH_CSN3, 69 GPIO0_D[2]/FLASH_CSN1, 70 GPIO0_D[6]/FLASH_CSN5, 71 GPIO1_A[0]/FLASH_CSN7/MDDR_TQ, 72 GPIO0_A[5]/FLASH_DQS, 73 GPIO0_D[5]/FLASH_CSN4, 74 GPIO4_B[2]/FLASH_DATA[10], 75 GPIO4_B[3]/FLASH_DATA[11], 78 GPIO3_B[3]/EMMC_DATA1, 79 GPIO3_B[1]/EMMC_CMD, 80 GPIO3_B[6]/EMMC_DATA4, 81 GPIO3_C[1]/EMMC_DATA7, 82 GPIO3_B[5]/EMMC_DATA3, 83 GPIO3_B[4]/EMMC_DATA2, 84 GPIO3_B[2]/EMMC_DATA0, 85 GPIO3_C[0]/EMMC_DATA6, 86 GPIO3_B[7]/EMMC_DATA5, 88 GPIO3_B[0]/EMMC_CLKOUT, 203 GPIO1_A[5]/EMMC_PWR_EN/PWM3, 246 GPIO6_A[7]
part F pins: 91 GPIO1_C[2]/SDMMC1_CMD, 93 GPIO1_C[7]/SDMMC1_CLKOUT, 95 GPIO1_C[4]/SDMMC1_DATA1, 96 GPIO1_C[3]/SDMMC1_DATA0, 97 GPIO1_C[6]/SDMMC1_DATA3, 98 GPIO1_C[5]/SDMMC1_DATA2, 103 GPIO1_D[3]/SDMMC0_DATA1, 104 GPIO1_D[1]/SDMMC0_CMD, 105 GPIO1_D[5]/SDMMC0_DATA3, 106 GPIO2_A[1]/SDMMC0_DATA7, 107 GPIO1_D[7]/SDMMC0_DATA5, 108 GPIO1_D[2]/SDMMC0_DATA0, 109 GPIO2_A[0]/SDMMC0_DATA6, 110 GPIO1_D[6]/SDMMC0_DATA4, 111 GPIO1_D[4]/SDMMC0_DATA2, 113 GPIO1_D[0]/SDMMC0_CLKOUT, 185 GPIO5_D[7], 193 GPIO2_A[2]/SDMMC0_DETECT_N, 204 GPIO2_A[3]/SDMMC0_WRITE_PRT/PWM2/UART1_SIR_OUT, 208 GPIO5_D[5]/SDMMC0_PWR_EN, 209 GPIO5_D[6]/SDMMC1_PWR_EN
part G pins: 126 GPIO4_C[7]/RMII_RXD0/MII_RXD0, 127 GPIO4_C[3]/RMII_TXD0/MII_TXD0, 128 GPIO4_C[6]/RMII_RXD1/MII_RXD1, 129 GPIO4_C[1]/RMII_TX_EN/MII_TX_EN, 130 GPIO4_C[0]/RMII_CLKOUT/RMII_CLKIN, 131 GPIO4_C[2]/RMII_TXD1/MII_TXD1, 132 GPIO4_C[5]/RMII_CRS_DVALID/MII_RXD_VALID, 133 GPIO4_C[4]/RMII_RX_ERR/MII_RX_ERR, 148 GPIO5_A[3]/MII_TX_CLKIN, 149 GPIO0_A[6]/MII_MD, 189 GPIO0_A[7]/MII_MDCLK, 236 GPIO5_A[2], 248 GPIO6_B[0], 253 GPIO5_A[1], 266 TRST_N, 267 TCK, 268 TDI, 269 TMS, 270 TDO
part H pins: 135 GPIO5_A[7]/HSADC_DATA2, 136 GPIO5_B[5]/HSADC_DATA8/TS_VALID, 137 GPIO5_A[5]/HSADC_DATA0, 138 GPIO5_B[1]/HSADC_DATA4, 139 GPIO5_B[0]/HSADC_DATA3, 140 GPIO5_A[6]/HSADC_DATA1, 141 GPIO5_B[3]/HSADC_DATA6, 142 GPIO5_B[2]/HSADC_DATA5, 143 GPIO5_B[4]/HSADC_DATA7, 144 GPIO5_A[4]/TS_SYNC, 145 GPIO5_B[6]/HSADC_DATA9/TS_FAIL, 146 GPIO5_B[7]/HSADC_CLKOUT/GPS_CLK, 247 GPIO6_B[3]
part I pins: 115 GPIO2_D[1]/I2S0_SCLK/MII_CRS, 116 GPIO4_D[6]/I2S0_LRCK_TX0, 117 GPIO2_D[0]/I2S0_CLK/MII_RX_CLKIN, 118 GPIO2_D[7]/I2S0_SDO3/MII_TXD3, 119 GPIO2_D[4]/I2S0_SDO0/MII_RXD2, 120 GPIO2_D[3]/I2S0_SDI/MII_COL, 121 GPIO4_D[7]/I2S0_LRCK_TX1, 122 GPIO2_D[6]/I2S0_SDO2/MII_TXD2, 123 GPIO2_D[5]/I2S0_SDO1/MII_RXD3, 124 GPIO2_D[2]/I2S0_LRCK_RX/MII_TX_ERR, 165 GPIO4_A[7]/SPDIF_TX, 167 GPIO1_A[3]/EMMC_DETECT_N/SPI1_CSN1, 169 GPIO2_C[6]/SPI1_TXD, 170 GPIO2_C[4]/SPI1_CLK, 171 GPIO2_C[3]/SPI0_RXD, 172 GPIO2_C[2]/SPI0_TXD, 173 GPIO2_C[7]/SPI1_RXD, 174 GPIO2_C[0]/SPI0_CLK, 175 GPIO2_C[1]/SPI0_CSN0, 176 GPIO2_C[5]/SPI1_CSN0, 177 GPIO1_A[6]/I2C1_SDA, 178 GPIO1_A[7]/I2C1_SCL, 192 GPIO1_A[4]/EMMC_WRITE_PRT/SPI0_CSN1, 196 GPIO2_B[7]/I2C0_SCL, 197 GPIO2_B[6]/I2C0_SDA, 205 GPIO5_D[3]/I2C2_SDA, 206 GPIO5_D[4]/I2C2_SCL, 212 GPIO2_B[2]/UART3_SIN, 213 GPIO1_B[6]/UART0_SIN, 214 GPIO2_A[5]/UART1_SOUT, 215 GPIO2_B[1]/UART2_SOUT, 216 GPIO2_B[3]/UART3_SOUT, 217 GPIO2_A[4]/UART1_SIN, 218 GPIO2_B[5]/UART3_RTS_N/I2C3_SCL, 219 GPIO2_B[4]/UART3_CTS_N/I2C3_SDA, 220 GPIO2_B[0]/UART2_SIN, 221 GPIO2_A[6]/UART2_CTS_N, 222 GPIO1_B[7]/UART0_SOUT, 223 GPIO2_A[7]/UART2_RTS_N, 224 GPIO1_C[1]/UART0_RTS_N/SDMMC1_WRITE_PRT, 225 GPIO1_C[0]/UART0_CTS_N/SDMMC1_DETECT_N, 227 GPIO3_A[0]/I2S1_CLK, 228 GPIO3_A[2]/I2S1_LRCK_RX, 229 GPIO3_A[1]/I2S1_SCLK, 230 GPIO3_A[3]/I2S1_SDI, 231 GPIO3_A[4]/I2S1_SDO, 232 GPIO3_A[5]/I2S1_LRCK_TX
part J pins: 23 SARADC_AIN[0], 24 SARADC_AIN[1], 25 SARADC_AIN[2], 26 SARADC_AIN[3], 179 GPIO6_C[3], 180 GPIO6_C[7], 181 GPIO6_C[4], 182 GPIO6_C[0], 183 GPIO4_D[0], 184 GPIO6_C[1], 186 GPIO6_C[2], 188 GPIO6_C[6], 190 GPIO4_D[1], 191 GPIO4_D[5], 194 GPIO4_D[4], 195 GPIO6_C[5], 198 GPIO4_D[2], 207 GPIO4_D[3], 210 GPIO5_D[2]/PWM1/UART1_SIR_IN, 234 GPIO6_A[4], 235 GPIO6_A[3], 237 GPIO6_B[7], 238 GPIO6_A[0], 239 GPIO6_B[6], 241 GPIO6_A[1], 242 GPIO6_A[5], 243 GPIO6_B[4], 244 GPIO6_A[2], 245 GPIO6_A[6], 249 GPIO5_A[0], 250 GPIO6_B[2], 251 GPIO6_B[1], 252 GPIO0_A[1], 254 GPIO0_A[0], 255 GPIO0_A[2], 256 GPIO0_A[4], 257 GPIO0_A[3], 258 GPIO4_A[3], 259 GPIO4_A[0], 260 GPIO4_A[1], 261 GPIO4_A[2], 262 GPIO4_A[4]
part K pins: 1 GND, 2 GND, 21 GND, 22 GND, 27 GND, 28 GND, 31 GND, 34 GND, 37 GND, 40 GND, 42 GND, 44 GND, 76 GND, 77 GND, 87 GND, 89 GND, 90 GND, 92 GND, 94 GND, 99 GND, 100 GND, 101 GND, 102 GND, 112 GND, 114 GND, 125 GND, 134 GND, 147 GND, 164 GND, 168 GND, 199 GND, 200 GND, 201 GND, 202 GND, 226 GND, 233 GND, 263 GND, 265 GND, 275 TopBoard_DET0, 276 TopBoard_DET1, 277 GND, 278 VB, 279 GND, 280 VCC18, 281 GND, 282 VCC25, 283 GND, 284 VCCA, 285 GND, 286 VCC, 287 GND, 288 GND, 289 VDD, 290 VDD, 291 VDD, 292 VDD, 293 GND, 294 GND, 295 VCCDR, 296 VCCDR, 297 VCCDR, 298 VCCDR, 299 GND, 300 GND, 301 GND, 302 GND, 303 GND, 304 GND, 306 GND, 308 GND, 310 GND, 312 GND, 314 GND, 316 GND, 318 GND, 320 GND, 322 GND, 324 GND, 326 GND, 328 GND, 330 GND, 332 GND, 334 GND, 336 GND, 338 GND, 340 GND, 342 GND, 344 GND, 346 GND, 348 GND, 350 GND, 352 GND, 354 GND, 356 GND, 358 GND, 360 GND, 361 GND, 362 GND, 375 GND, 377 GND, 379 GND, 381 GND, 383 GND, 384 GND, 385 GND, 399 GND, 400 GND

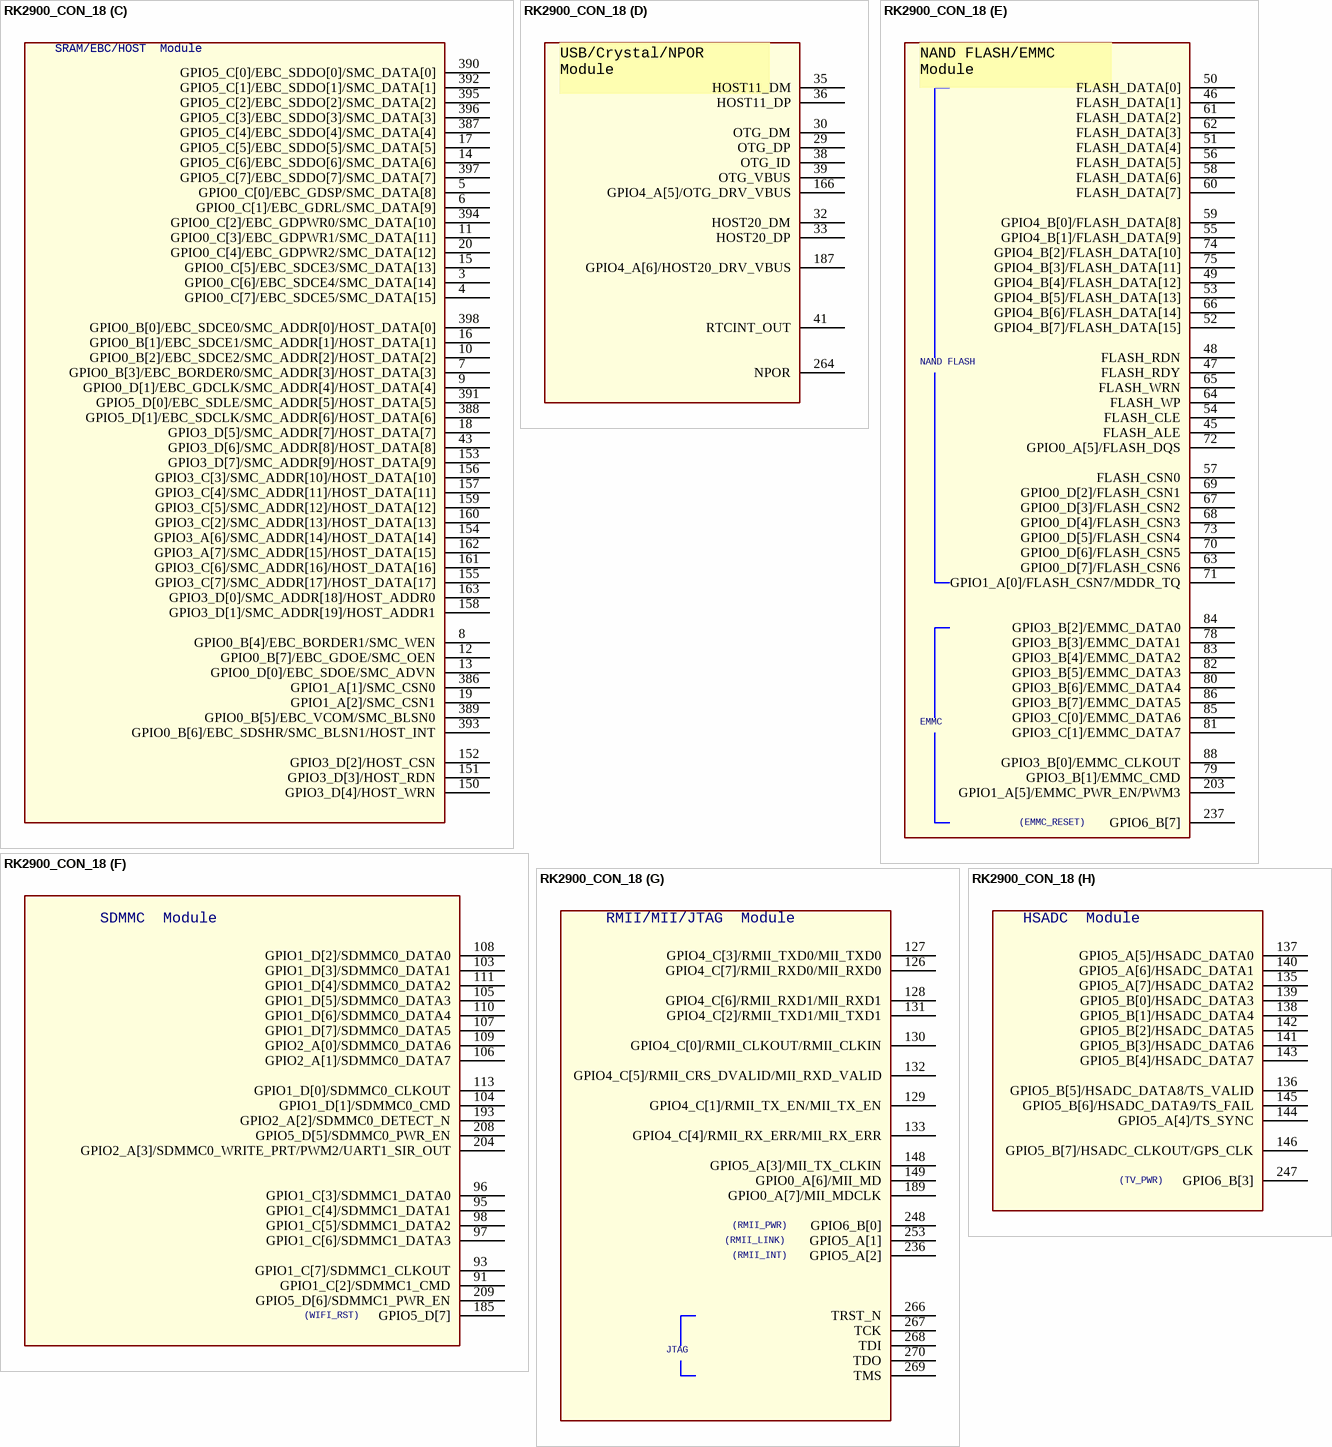
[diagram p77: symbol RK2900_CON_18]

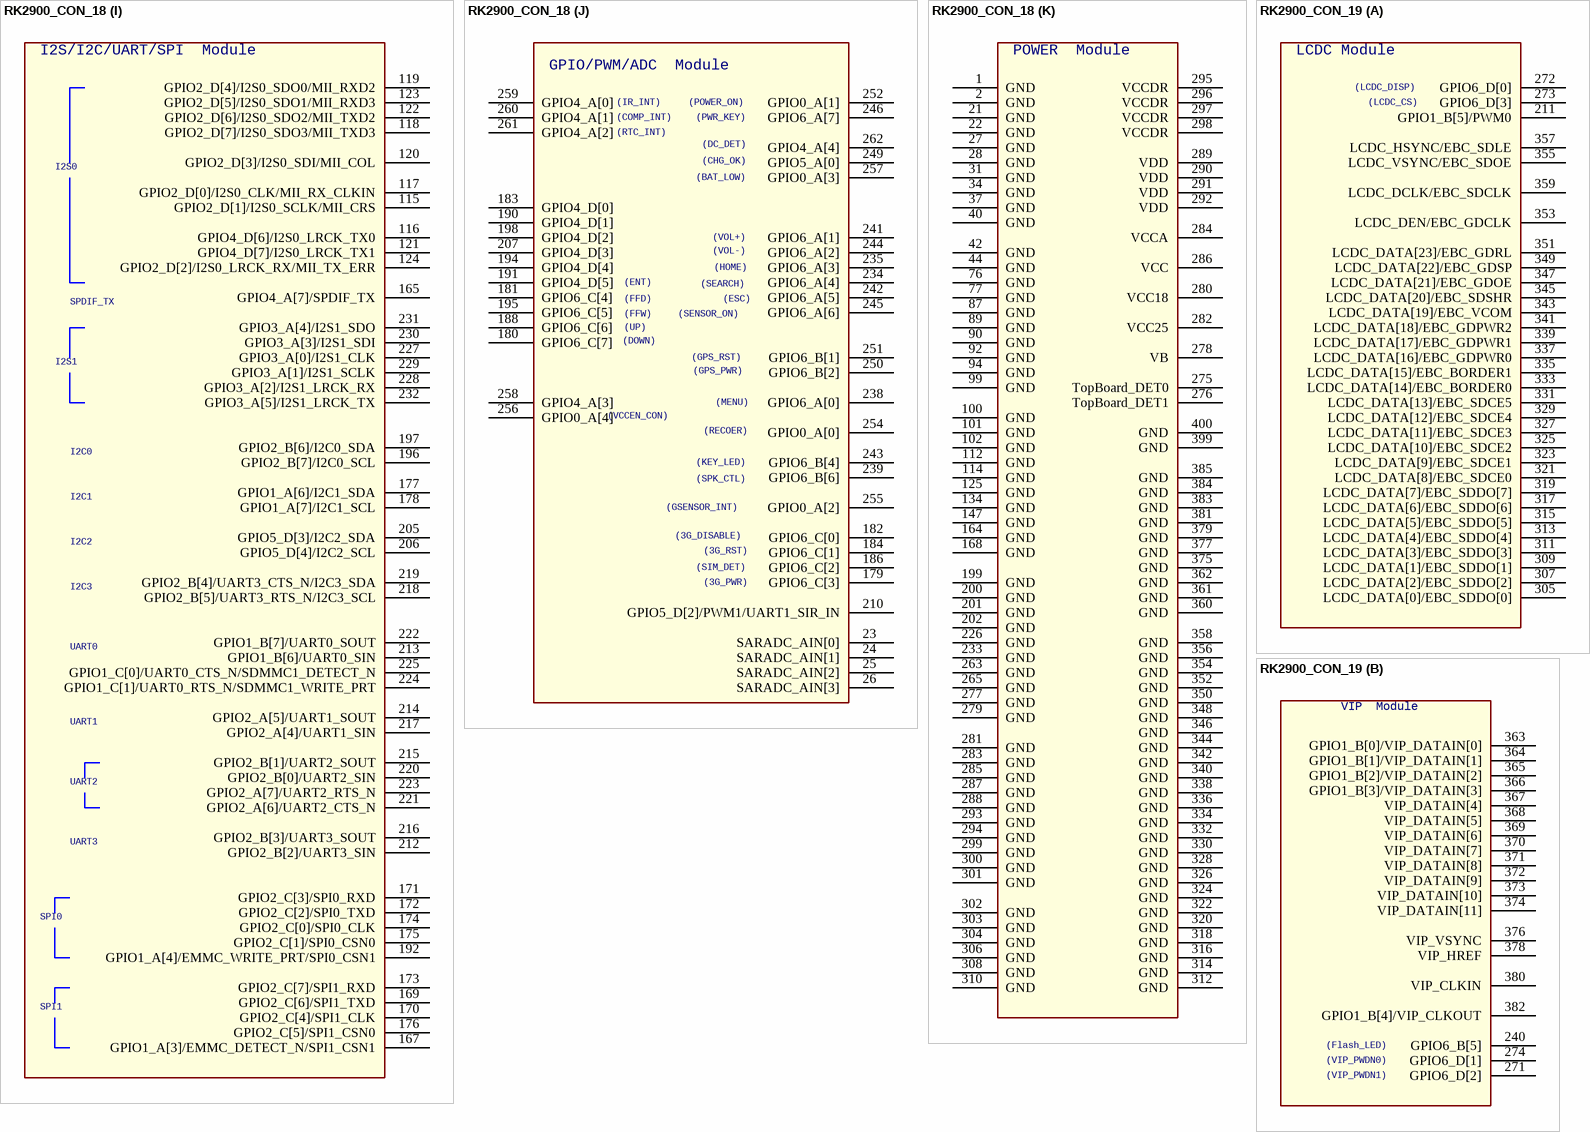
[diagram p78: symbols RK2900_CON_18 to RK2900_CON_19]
